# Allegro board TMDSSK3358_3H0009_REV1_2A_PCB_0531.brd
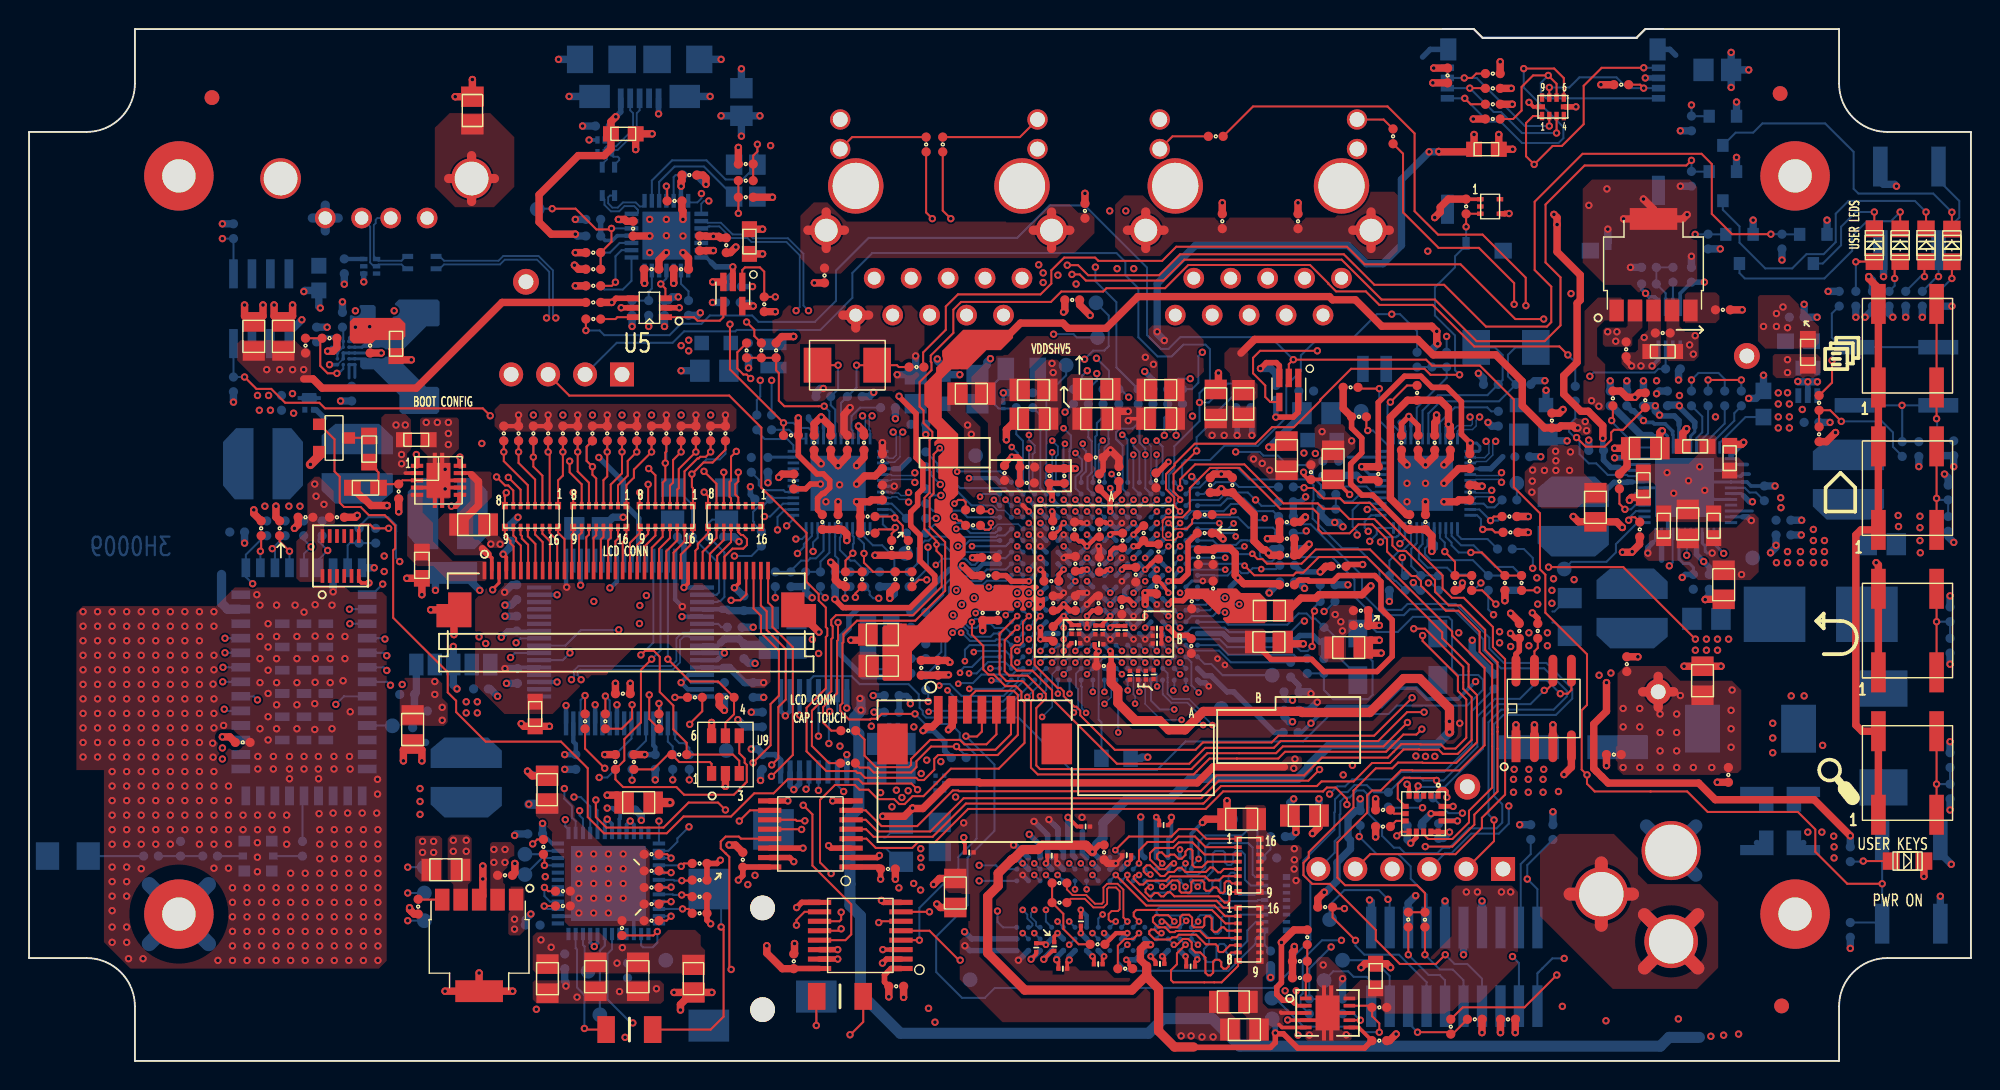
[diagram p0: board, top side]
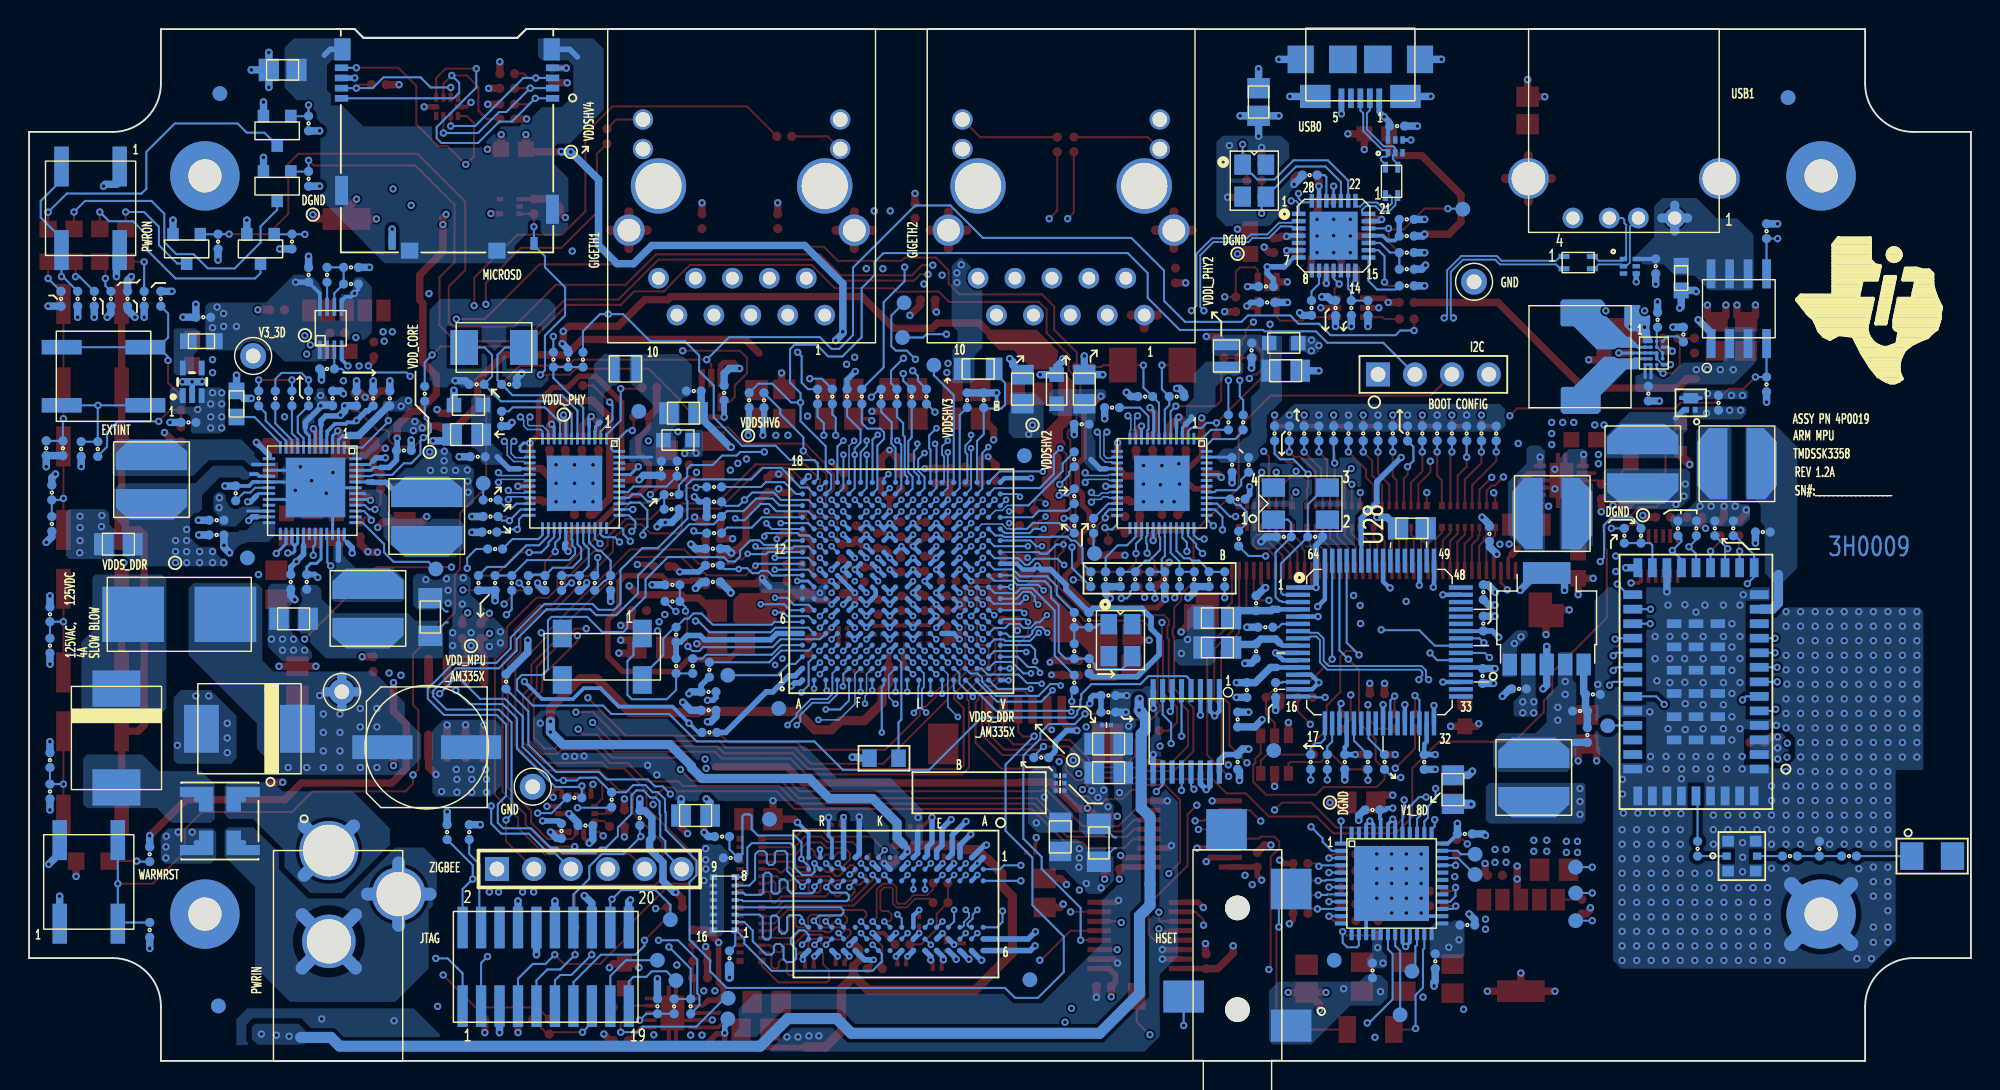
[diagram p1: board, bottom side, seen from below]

Outline 133.51 x 71.01 mm; copper layers: TOP, LY2_GND1, LY3_SIG1, LYR4_PWR1, LY5_PWR2, LY6_SIG2, LY7_GND2, BOTTOM. Coordinates in mm from the lower left corner of the outline.
Outline path: 0,63.93 3.95,63.93 arc(6.3,64.9) 7.28,67.25 7.28,71.01 99.33,71.01 99.93,70.41 110.53,70.41 111.13,71.01 124.45,71.01 124.45,67.25 arc(125.42,64.9) 127.78,63.93 133.51,63.93 133.51,7.08 127.78,7.08 arc(125.42,6.11) 124.45,3.76 124.45,0 7.28,0 7.28,3.76 arc(6.3,6.11) 3.95,7.08 0,7.08 0,63.93

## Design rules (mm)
net group AM335X_RGMII1_RXCLK: nets AM335X_RGMII1_RXCLK ETH1_RXCLK
net group AM335X_RGMII1_RXD0: nets AM335X_RGMII1_RXD0 ETH1_RXD0
net group AM335X_RGMII1_RXD1: nets AM335X_RGMII1_RXD1 ETH1_RXD1
net group AM335X_RGMII1_RXD2: nets AM335X_RGMII1_RXD2 ETH1_RXD2
net group AM335X_RGMII1_RXD3: nets AM335X_RGMII1_RXD3 ETH1_RXD3
net group AM335X_RGMII1_RXDV: nets AM335X_RGMII1_RXDV ETH1_RXDV
net group AM335X_RGMII1_TXCLK: nets AM335X_RGMII1_TXCLK RGMII1_TXCLK
net group AM335X_RGMII1_TXD0: nets AM335X_RGMII1_TXD0 RGMII1_TXD0
net group AM335X_RGMII1_TXD1: nets AM335X_RGMII1_TXD1 RGMII1_TXD1
net group AM335X_RGMII1_TXD2: nets AM335X_RGMII1_TXD2 RGMII1_TXD2
net group AM335X_RGMII1_TXD3: nets AM335X_RGMII1_TXD3 RGMII1_TXD3
net group AM335X_RGMII1_TXEN: nets AM335X_RGMII1_TXEN RGMII1_TXEN
net group AM335X_RGMII2_RXCLK: nets AM335X_RGMII2_RXCLK ETH2_RXCLK
net group AM335X_RGMII2_RXD0: nets AM335X_RGMII2_RXD0 ETH2_RXD0
net group AM335X_RGMII2_RXD1: nets AM335X_RGMII2_RXD1 ETH2_RXD1
net group AM335X_RGMII2_RXD2: nets AM335X_RGMII2_RXD2 ETH2_RXD2
net group AM335X_RGMII2_RXD3: nets AM335X_RGMII2_RXD3 ETH2_RXD3
net group AM335X_RGMII2_RXDV: nets AM335X_RGMII2_RXDV ETH2_RXDV
net group AM335X_RGMII2_TXCLK: nets AM335X_RGMII2_TXCLK RGMII2_TXCLK
net group AM335X_RGMII2_TXD0: nets AM335X_RGMII2_TXD0 RGMII2_TXD0
net group AM335X_RGMII2_TXD1: nets AM335X_RGMII2_TXD1 RGMII2_TXD1
net group AM335X_RGMII2_TXD2: nets AM335X_RGMII2_TXD2 RGMII2_TXD2
net group AM335X_RGMII2_TXD3: nets AM335X_RGMII2_TXD3 RGMII2_TXD3
net group AM335X_RGMII2_TXEN: nets AM335X_RGMII2_TXEN RGMII2_TXEN
net group BYTE2: nets DDR_DQS1 DDR_DQSN1
net group CLK_25M: nets CLK_25M CLK_25M_R
net group ETHER2_D0: nets ETHER2_D0N ETHER2_D0P
net group ETHER2_D1: nets ETHER2_D1N ETHER2_D1P
net group ETHER2_D2: nets ETHER2_D2N ETHER2_D2P
net group ETHER2_D3: nets ETHER2_D3N ETHER2_D3P
net group ETHER_D0: nets ETHER_D0N ETHER_D0P
net group ETHER_D1: nets ETHER_D1N ETHER_D1P
net group ETHER_D2: nets ETHER_D2N ETHER_D2P
net group ETHER_D3: nets ETHER_D3N ETHER_D3P
net group HUB_USB_UP: nets HUB_USBDM_UP HUB_USBDP_UP
net group USB0_DP1: nets USB0_DM USB0_DP
net group USB0_UP_DP1: nets USBDM_UP USBDP_UP
net group USB1_CONN_DP_1: nets USB1_CONN_DM USB1_CONN_DP
net group USB1_DIP1: nets USB1_DM USB1_DP
net group USB_FT_DP1: nets FT_DM FT_DP
net group ADD: nets DDR_A0 DDR_A1 DDR_A2 DDR_A3 DDR_A4 DDR_A5 DDR_A6 DDR_A7 DDR_A8 DDR_A9 DDR_A10 DDR_A11 DDR_A12 DDR_A13 DDR_A14 DDR_BA0 DDR_BA1 DDR_BA2 DDR_CASN DDR_CKE DDR_CSN DDR_ODT DDR_RASN DDR_RESETN DDR_WEN
net group AUDIO: nets AM335X_AUDA_DIN AM335X_AUDA_DOUT AM335X_AUDA_FSX AM335X_XDMA_EVENT_INTR0 AM335X_XDMA_EVENT_INTR1 AUD_RESETN HD_SPKRM HD_SPKRP HS_SPKRM HS_SPKRP SYS_WARMRESETN
net group BYTE0: nets DDR_D0 DDR_D1 DDR_D2 DDR_D3 DDR_D4 DDR_D5 DDR_D6 DDR_D7 DDR_DQM0
net group BYTE1: nets DDR_D8 DDR_D9 DDR_D10 DDR_D11 DDR_D12 DDR_D13 DDR_D14 DDR_D15 DDR_DQM1 DDR_DQS0 DDR_DQSN0
net group CLK: nets AM335X_AUDA_BCLK AM335X_LCD_PCLK AM335X_MCASP0_ACLKX AM335X_MCASP0_AHCLKR AM335X_MCASP0_AHCLKX AM335X_MMC0_CLK AM335X_OSC1_IN AM335X_OSC1_OUT AM335X_RGMII1_MDIO_CLK AM335X_SPI0_SCLK CCLK COM_SLOW_CLK COM_SLOW_CLK_XO COMAUD_CLK ETH_MDIO_CLK JTAG_TCK MMC1_CLK
net group DDR: nets N21689199 N24290596 N24874310 REFIN_DDR
net group LCD_IF: nets AM335X_LCD_AC_BIAS_EN AM335X_LCD_DATA0 AM335X_LCD_DATA1 AM335X_LCD_DATA2 AM335X_LCD_DATA3 AM335X_LCD_DATA4 AM335X_LCD_DATA5 AM335X_LCD_DATA6 AM335X_LCD_DATA7 AM335X_LCD_DATA8 AM335X_LCD_DATA9 AM335X_LCD_DATA10 AM335X_LCD_DATA11 AM335X_LCD_DATA12 AM335X_LCD_DATA13 AM335X_LCD_DATA14 AM335X_LCD_DATA15 AM335X_LCD_DATA16 AM335X_LCD_DATA17 AM335X_LCD_DATA18 AM335X_LCD_DATA19 AM335X_LCD_DATA20 AM335X_LCD_DATA21 AM335X_LCD_DATA22 AM335X_LCD_DATA23 AM335X_LCD_DISEN AM335X_LCD_HSYNC AM335X_LCD_VSYNC AM335X_XLEFT AM335X_XRIGHT AM335X_YDOWN AM335X_YUP CBB0 CBB1 CBB2 CBB3 CBB4 CBB5 CBB6 CBB7 CBG0 CBG1 CBG2 CBG3 CBG4 CBG5 CBG6 CBG7 CBR0 CBR1 CBR2 CBR3 CBR4 CBR5 CBR6 CBR7 CDEN CHSYNC CVSYNC DISEN LCD_BACKLIGHTEN
net group POWER: nets CAP_VDD_SRAM_CORE DDR_VREF GNDA_ADC VBUS_DET
net group PWR: nets CAP_VBB_MPU CAP_VDD_SRAM_MPU CHASSIS_USB0 FT_VBUS GND_IN GND_OSC0 GND_OSC1 KEYPAD_PWRA LED+ LED- N21904036 N21904046 N27067217 PWR_SMPS1 PWR_SMPS1_FB PWR_SMPS2 PWR_SWIO USB_DC V5_0D VAUX1 VCOM_BATFB VDD_1V8FT VDD_FTVPHY VDD_FTVPLL VDD_MPU_AM335X VDD_RTC VDDH_PHY VDDH_PHY2 VDDL_PHY2 VDDMPU_MON VDDS_DDR3_AM335X VDDSHV1 VETH2_AVDD_3_3 VETH2_VDDIO VETH_VDDIO VRTC_PMIC
net group RF_SIGNALS: nets N21930813 N21931209 N21931218 N23618396

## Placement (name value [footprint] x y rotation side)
A1  LBEE5ZSTNC-523  [MOD17X10-62P]  18.9 26.09 0 bottom
ANT1  LDA312G7313F-237  [SMD1206-ANTENNA]  2.67 14.1 180 bottom
C1  0.1uF  [SM-7351-CAP-0402]  97.54 67.82 270 top
C2  4.7uF  [SM-7351-CAP-0603]  40.86 63.8 0 top
C3  4.7uF  [SM-7351-CAP-0603]  100.2 62.74 0 top
C4  18pF, 10V, 2%  [SM-7351-CAP-0402]  49.28 61.72 0 top
C5  0.1uF  [SM-7351-CAP-0402]  45.4 60.96 0 top
C6  18pF, 10V, 2%  [SM-7351-CAP-0402]  49.28 59.44 180 top
C7  1uF  [SM-7351-CAP-0402]  44.38 59.18 0 top
C8  0.1uF  [SM-7351-CAP-0402]  72.6 58.5 270 top
C9  0.1uF  [SM-7351-CAP-0402]  82.04 57.78 270 top
C10  0.1uF  [SM-7351-CAP-0402]  87.25 57.78 270 top
C11  0.1uF  [SM-7351-CAP-0402]  41.53 57.28 270 top
C12  4.7uF  [SM-7351-CAP-0603]  49.53 56.39 270 top
C13  0.1uF  [SM-7351-CAP-0402]  46.1 56.26 270 top
C14  1uF  [SM-7351-CAP-0402]  47.94 56.13 270 top
C15  0.1uF  [SM-7351-CAP-0402]  42.8 54.48 0 top
C16  0.1uF  [SM-7351-CAP-0402]  44.83 54.48 0 top
C17  0.1uF  [SM-7351-CAP-0402]  54.69 54.05 90 top
C18  0.1uF  [SM-7351-CAP-0402]  71.72 52.37 0 top
C19  0.01uF  [SM-7351-CAP-0402]  116.46 51.69 0 top
C20  0.01uF  [SM-7351-CAP-0402]  112.33 50.1 180 top
C21  22uF  [SM-7351-CAP-0805]  15.45 49.86 90 top
C22  22uF  [SM-7351-CAP-0805]  17.48 49.86 90 top
C23  4.7uF  [SM-7351-CAP-0603]  25.23 49.35 270 top
C24  0.1uF  [SM-7351-CAP-0402]  23.45 49.23 270 top
C25  2.2uF, 10V  [SM-7351-CAP-0402]  109.81 48.97 270 top
C26  4.7uF  [SM-7351-CAP-0603]  112.33 48.83 180 top
C27  10uF  [SM-7351-CAP-0805]  81.59 45.21 90 top
C28  10uF  [SM-7351-CAP-0805]  69.09 44.2 180 top
C29  10uF  [SM-7351-CAP-0805]  73.41 44.2 0 top
C30  10uF  [SM-7351-CAP-0805]  77.8 44.2 180 top
C31  2.2uF  [SM-7351-CAP-0402]  104.71 44.07 90 top
C32  1uF  [SM-7351-CAP-0402]  123.08 43.12 270 top
C33  4.7uF  [SM-7351-CAP-0603]  26.63 42.75 0 top
C34  0.1uF  [SM-7351-CAP-0402]  53.97 42.55 270 top
C35  1uF  [SM-7351-CAP-0402]  55.12 42.55 270 top
C36  0.1uF  [SM-7351-CAP-0402]  56.26 42.55 270 top
C37  1uF  [SM-7351-CAP-0402]  57.4 42.55 270 top
C38  0.1uF  [SM-7351-CAP-0402]  94.36 42.55 270 top
C39  1uF  [SM-7351-CAP-0402]  95.5 42.55 270 top
C40  0.1uF  [SM-7351-CAP-0402]  96.65 42.55 270 top
C41  1uF  [SM-7351-CAP-0402]  97.72 42.55 270 top
C42  4.7uF  [SM-7351-CAP-0603]  114.55 42.29 0 top
C43  10uF  [SM-7351-CAP-0805]  111.12 42.16 180 top
C44  10uF  [SM-7351-CAP-0805]  86.46 41.66 90 top
C45  0.01uF  [SM-7351-CAP-0402]  73.34 41.53 0 top
C46  4.7uF  [SM-7351-CAP-0603]  116.92 41.48 270 top
C47  0.1uF  [SM-7351-CAP-0402]  58.67 41.27 270 top
C48  0.1uF  [SM-7351-CAP-0402]  99.06 41.27 270 top
C49  10uF  [SM-7351-CAP-0805]  89.66 41.02 90 top
C50  0.01uF  [SM-7351-CAP-0402]  68.63 40.87 180 top
C51  0.01uF  [SM-7351-CAP-0402]  88.14 40.51 90 top
C52  0.01uF  [SM-7351-CAP-0402]  67.07 40.46 90 top
C53  0.01uF  [SM-7351-CAP-0402]  74.93 40.39 90 top
C54  0.1uF  [SM-7351-CAP-0402]  92.77 40.39 270 top
C55  0.01uF  [SM-7351-CAP-0402]  70.16 40.26 90 top
C56  0.01uF  [SM-7351-CAP-0402]  71.18 40.26 90 top
C57  0.01uF  [SM-7351-CAP-0402]  77.48 39.95 90 top
C58  0.1uF  [SM-7351-CAP-0402]  52.58 39.88 270 top
C59  0.01uF  [SM-7351-CAP-0402]  73.59 39.88 90 top
C60  0.01uF  [SM-7351-CAP-0402]  68.61 39.78 180 top
C61  0.01uF  [SM-7351-CAP-0402]  81.21 39.62 90 top
C62  0.01uF  [SM-7351-CAP-0402]  82.73 39.62 90 top
C63  4.7uF  [SM-7351-CAP-0603]  111 39.62 90 top
C64  47nF  [SM-7351-CAP-0402]  25.41 39.19 270 top
C65  0.1uF  [SM-7351-CAP-0402]  58.67 39.12 270 top
C66  0.1uF  [SM-7351-CAP-0402]  99.06 39.12 270 top
C67  10uF  [SM-7351-CAP-0805]  107.7 38.1 270 top
C68  470pF  [SM-7351-CAP-0402]  57.66 37.47 180 top
C69  0.01uF  [SM-7351-CAP-0402]  19.01 37.41 180 top
C70  0.01uF  [SM-7351-CAP-0402]  21.16 37.41 0 top
C71  0.1uF  [SM-7351-CAP-0402]  55.63 37.08 90 top
C72  0.01uF  [SM-7351-CAP-0402]  86.49 37.08 0 top
C73  0.1uF  [SM-7351-CAP-0402]  96.01 37.08 90 top
C74  10uF  [SM-7351-CAP-0805]  114.05 36.96 90 top
C75  4.7uF  [SM-7351-CAP-0805]  30.56 36.91 0 top
C76  4.7uF  [SM-7351-CAP-0603]  112.39 36.83 90 top
C77  4.7uF  [SM-7351-CAP-0603]  115.82 36.83 90 top
C78  0.01uF  [SM-7351-CAP-0402]  70.38 36.65 270 top
C79  0.01uF  [SM-7351-CAP-0402]  71.88 36.58 270 top
C80  0.01uF  [SM-7351-CAP-0402]  73.59 36.58 270 top
C81  470pF  [SM-7351-CAP-0402]  57.66 36.32 180 top
C82  0.01uF  [SM-7351-CAP-0402]  76.64 36.32 270 top
C83  1uF  [SM-7351-CAP-0402]  80.83 36.32 0 top
C84  0.01uF  [SM-7351-CAP-0402]  86.49 35.94 0 top
C85  0.01uF  [SM-7351-CAP-0402]  75.18 35.81 270 top
C86  0.01uF  [SM-7351-CAP-0402]  77.65 35.05 90 top
C87  0.01uF  [SM-7351-CAP-0402]  86.49 34.8 0 top
C88  0.001uF  [SM-7351-CAP-0402]  80.39 34.67 90 top
C89  0.1uF  [SM-7351-CAP-0402]  81.41 34.67 90 top
C90  0.01uF  [SM-7351-CAP-0402]  66.02 34.65 180 top
C91  0.01uF  [SM-7351-CAP-0402]  71.94 34.21 270 top
C92  0.01uF  [SM-7351-CAP-0402]  73.59 34.16 270 top
C93  0.01uF  [SM-7351-CAP-0402]  90.04 34.04 0 top
C94  0.01uF  [SM-7351-CAP-0402]  76.09 33.46 90 top
C95  0.01uF  [SM-7351-CAP-0402]  65.97 33.4 180 top
C96  0.01uF  [SM-7351-CAP-0402]  70.29 33.02 0 top
C97  10uF  [SM-7351-CAP-0805]  116.52 32.77 270 top
C98  0.01uF  [SM-7351-CAP-0402]  77.53 32.64 90 top
C99  0.01uF  [SM-7351-CAP-0402]  79.94 31.62 270 top
C100  0.01uF  [SM-7351-CAP-0402]  70.42 31.5 270 top
C101  0.01uF  [SM-7351-CAP-0402]  71.94 31.5 270 top
C102  0.01uF  [SM-7351-CAP-0402]  73.53 31.5 270 top
C103  0.01uF  [SM-7351-CAP-0402]  75.13 31.24 90 top
C104  0.01uF  [SM-7351-CAP-0402]  91.57 30.99 0 top
C105  0.01uF  [SM-7351-CAP-0402]  65.56 30.84 270 top
C106  0.01uF  [SM-7351-CAP-0402]  66.61 30.84 270 top
C107  0.01uF  [SM-7351-CAP-0402]  91.57 29.97 0 top
C108  0.1uF, 6.3V  [SMD0201]  77.55 29.77 0 top
C109  0.1uF, 6.3V  [SMD0201]  71.69 29.69 90 top
C110  0.1uF, 6.3V  [SMD0201]  72.19 29.69 90 top
C111  0.1uF, 6.3V  [SMD0201]  73.31 29.67 90 top
C112  0.1uF, 6.3V  [SMD0201]  73.82 29.67 90 top
C113  0.1uF, 6.3V  [SMD0201]  74.86 29.64 90 top
C114  0.1uF, 6.3V  [SMD0201]  75.37 29.64 90 top
C115  0.01uF  [SM-7351-CAP-0402]  102.46 29.59 90 top
C116  0.01uF  [SM-7351-CAP-0402]  70.42 29.39 90 top
C117  10uF  [SM-7351-CAP-0805]  58.67 29.34 180 top
C118  0.1uF, 6.3V  [SMD0201]  77.55 29.26 0 top
C119  0.1uF, 6.3V  [SMD0201]  71.96 28.75 180 top
C120  0.1uF, 6.3V  [SMD0201]  77.55 28.73 0 top
C121  0.1uF, 6.3V  [SMD0201]  73.56 28.68 180 top
C122  1uF  [SM-7351-CAP-0402]  79.91 28.55 270 top
C123  10uF  [SM-7351-CAP-0805]  90.74 28.45 0 top
C124  0.1uF  [SM-7351-CAP-0402]  109.85 27.3 90 top
C125  0.1uF  [SM-7351-CAP-0402]  73.89 27.18 180 top
C126  0.01uF  [SM-7351-CAP-0402]  61.34 27.05 90 top
C127  0.01uF  [SM-7351-CAP-0402]  62.48 27.05 90 top
C128  0.1uF, 6.3V  [SMD0201]  77.32 26.59 270 top
C129  0.1uF, 6.3V  [SMD0201]  75.69 26.54 270 top
C130  0.1uF, 6.3V  [SMD0201]  76.25 26.54 270 top
C131  0.1uF, 6.3V  [SMD0201]  76.78 26.54 270 top
C132  10uF  [SM-7351-CAP-0805]  115.06 26.16 90 top
C133  0.1uF  [SM-7351-CAP-0402]  40.82 25.27 180 top
C134  4.7uF  [SM-7351-CAP-0603]  34.8 23.88 270 top
C135  2.2uF  [SM-7351-CAP-0805]  26.37 22.81 270 top
C136  0.01uF  [SM-7351-CAP-0402]  14.69 21.92 0 top
C137  1uF  [SM-7351-CAP-0402]  108.97 21.08 180 top
C138  0.1uF  [SM-7351-CAP-0402]  116.84 19.69 270 top
C139  10uF  [SM-7351-CAP-0805]  41.91 17.78 0 top
C140  10uF  [SM-7351-CAP-0805]  87.69 16.89 0 top
C141  10uF  [SM-7351-CAP-0805]  83.37 16.64 180 top
C142  0.1uF, 6.3V  [SMD0201]  78.01 16.23 0 top
C143  0.1uF, 6.3V  [SMD0201]  72.64 16.13 0 top
C144  0.1uF, 6.3V  [SMD0201]  64.64 14.35 0 top
C145  0.1uF  [SM-7351-CAP-0402]  73.91 14.35 270 top
C146  0.1uF  [SM-7351-CAP-0402]  42.8 14.22 180 top
C147  0.1uF, 6.3V  [SMD0201]  75.47 14.15 180 top
C148  0.1uF, 6.3V  [SMD0201]  70.31 14.12 0 top
C149  0.01uF  [SM-7351-CAP-0402]  49.07 13.84 90 top
C150  0.1uF  [SM-7351-CAP-0402]  46.1 13.59 0 top
C151  0.01uF  [SM-7351-CAP-0402]  59.05 13.21 0 top
C152  2.2uF  [SM-7351-CAP-0805]  28.66 13.16 180 top
C153  0.1uF  [SM-7351-CAP-0402]  42.8 13.08 180 top
C154  1uF  [SM-7351-CAP-0402]  32.72 12.78 0 top
C155  0.1uF  [SM-7351-CAP-0402]  46.1 12.45 0 top
C156  0.01uF  [SM-7351-CAP-0402]  42.8 11.94 180 top
C157  0.01uF  [SM-7351-CAP-0402]  36.7 11.68 0 top
C158  10uF  [SM-7351-CAP-0805]  63.68 11.56 90 top
C159  0.01uF  [SM-7351-CAP-0402]  46.1 11.3 0 top
C160  0.01uF  [SM-7351-CAP-0402]  42.8 10.79 180 top
C161  0.01uF  [SM-7351-CAP-0402]  36.7 10.67 0 top
C162  0.01uF  [SM-7351-CAP-0402]  26.75 10.62 270 top
C163  0.01uF  [SM-7351-CAP-0402]  46.1 10.16 0 top
C164  0.01uF  [SM-7351-CAP-0402]  42.8 9.65 180 top
C165  0.1uF, 6.3V  [SMD0201]  72.32 9.6 270 top
C166  0.01uF  [SM-7351-CAP-0402]  40.77 9.14 90 top
C167  0.1uF  [SM-7351-CAP-0402]  73.46 8.03 0 top
C168  0.1uF, 6.3V  [SMD0201]  70.48 7.87 90 top
C169  0.1uF, 6.3V  [SMD0201]  69.25 7.8 90 top
C170  0.01uF  [SM-7351-CAP-0402]  52.58 6.86 90 top
C171  0.001uF  [SM-7351-CAP-0402]  87.38 6.86 180 top
C172  0.1uF, 6.3V  [SMD0201]  77.76 6.68 0 top
C173  0.1uF, 6.3V  [SMD0201]  73.51 6.65 180 top
C174  0.1uF, 6.3V  [SMD0201]  79.86 6.5 0 top
C175  0.1uF, 6.3V  [SMD0201]  71.08 6.35 0 top
C176  4.7uF  [SM-7351-CAP-0603]  92.58 5.84 90 top
C177  10uF  [SM-7351-CAP-0805]  38.94 5.79 270 top
C178  10uF  [SM-7351-CAP-0805]  41.87 5.79 270 top
C179  10uF  [SM-7351-CAP-0805]  35.64 5.66 270 top
C180  0.01uF  [SM-7351-CAP-0402]  59.62 5.14 0 top
C181  47uF  [SM-7351-CAP-1206]  55.75 4.45 0 top
C182  10uF  [SM-7351-CAP-0805]  82.8 4.06 180 top
C183  0.1uF  [SM-7351-CAP-0402]  99.4 2.87 0 top
C184  0.01uF  [SM-7351-CAP-0402]  101.69 2.87 180 top
C185  47uF  [SM-7351-CAP-1206]  41.27 2.16 180 top
C186  10uF  [SM-7351-CAP-0805]  83.57 2.16 180 top
C187  0.1uF  [SM-7351-CAP-0402]  92.84 1.4 0 top
C188  0.01uF  [SM-7351-CAP-0402]  39.45 64.34 180 bottom
C189  0.1uF  [SM-7351-CAP-0402]  38.79 55.63 180 bottom
C190  0.01uF  [SM-7351-CAP-0402]  21.67 54.69 270 bottom
C191  0.01uF  [SM-7351-CAP-0402]  111.38 54.61 180 bottom
C192  0.01uF  [SM-7351-CAP-0402]  114.3 54.1 90 bottom
C193  4.7uF  [SM-7351-CAP-0603]  19.92 53.87 270 bottom
C194  0.1uF  [SM-7351-CAP-0402]  48.39 52.2 0 bottom
C195  1uF  [SM-7351-CAP-0402]  45.34 51.82 270 bottom
C196  0.1uF  [SM-7351-CAP-0402]  43.69 51.82 90 bottom
C197  1uF  [SM-7351-CAP-0402]  121.54 51.18 0 bottom
C198  0.1uF  [SM-7351-CAP-0402]  21.55 51 90 bottom
C199  0.1uF  [SM-7351-CAP-0402]  49.46 48.89 270 bottom
C200  10uF  [SM-7351-CAP-0805]  47.12 47.5 180 bottom
C201  27pF  [SM-7351-CAP-0402]  102.74 46.56 180 bottom
C202  27pF  [SM-7351-CAP-0402]  100.51 46.56 0 bottom
C203  10uF  [SM-7351-CAP-0805]  65.21 46.23 90 bottom
C204  10uF  [SM-7351-CAP-0805]  60.96 46.23 90 bottom
C205  0.1uF  [SM-7351-CAP-0402]  87.81 46.1 180 bottom
C206  0.01uF  [SM-7351-CAP-0402]  85.72 45.97 90 bottom
C207  2.2uF, 10V  [SM-7351-CAP-0402]  22.18 45.92 270 bottom
C208  27pF  [SM-7351-CAP-0402]  56.77 45.72 180 bottom
C209  27pF  [SM-7351-CAP-0402]  54.61 45.72 0 bottom
C210  2.2uF  [SM-7351-CAP-0402]  112.65 45.59 90 bottom
C211  2.2uF  [SM-7351-CAP-0402]  111 45.59 90 bottom
C212  2.2uF  [SM-7351-CAP-0402]  109.85 45.59 90 bottom
C213  2.2uF  [SM-7351-CAP-0402]  108.71 45.59 90 bottom
C214  0.1uF  [SM-7351-CAP-0402]  67.88 45.47 90 bottom
C215  0.01uF  [SM-7351-CAP-0402]  17.35 45.29 90 bottom
C216  10uF  [SM-7351-CAP-0805]  88.52 44.58 180 bottom
C217  1uF  [SM-7351-CAP-0402]  122.55 43.94 0 bottom
C218  0.1uF  [SM-7351-CAP-0402]  61.14 43.81 0 bottom
C219  10uF  [SM-7351-CAP-0805]  103.43 43.1 0 bottom
C220  1uF  [SM-7351-CAP-0402]  132.33 42.16 270 bottom
C221  2.2uF  [SM-7351-CAP-0402]  107.75 42.01 180 bottom
C222  0.1uF  [SM-7351-CAP-0402]  102.67 41.58 0 bottom
C223  0.1uF  [SM-7351-CAP-0402]  50.8 41.02 270 bottom
C224  0.1uF  [SM-7351-CAP-0402]  90.04 40.77 270 bottom
C225  0.01uF  [SM-7351-CAP-0402]  119.31 39.06 90 bottom
C226  470pF  [SM-7351-CAP-0402]  101.78 37.47 0 bottom
C227  2.2uF  [SM-7351-CAP-0402]  120.62 37.21 0 bottom
C228  1uF  [SM-7351-CAP-0402]  131.95 36.96 270 bottom
C229  470pF  [SM-7351-CAP-0402]  101.86 36.4 0 bottom
C230  0.01uF  [SM-7351-CAP-0402]  14.31 36.4 0 bottom
C231  0.01uF  [SM-7351-CAP-0402]  33.1 36.27 90 bottom
C232  2.2uF  [SM-7351-CAP-0402]  120.62 36.2 0 bottom
C233  27pF  [SM-7351-CAP-0402]  47.24 36.07 180 bottom
C234  27pF  [SM-7351-CAP-0402]  45.08 36.07 0 bottom
C235  10uF  [SM-7351-CAP-0805]  127.38 35.56 0 bottom
C236  0.01uF  [SM-7351-CAP-0402]  86.5 35.25 0 bottom
C237  470pF  [SM-7351-CAP-0402]  59.49 33.15 270 bottom
C238  2.2uF  [SM-7351-CAP-0402]  115.53 32.97 270 bottom
C239  0.01uF  [SM-7351-CAP-0402]  86.5 32.96 0 bottom
C240  470pF  [SM-7351-CAP-0402]  102.62 32.89 270 bottom
C241  0.1uF  [SM-7351-CAP-0402]  33.53 32.26 90 bottom
C242  0.1uF  [SM-7351-CAP-0402]  49.15 31.5 90 bottom
C243  1uF  [SM-7351-CAP-0402]  132.08 30.73 90 bottom
C244  10uF  [SM-7351-CAP-0805]  115.33 30.42 0 bottom
C245  18pF, 50V  [SM-7351-CAP-0402]  60.64 30.35 270 bottom
C246  0.1uF  [SM-7351-CAP-0402]  33.53 30.1 90 bottom
C247  22pF  [SM-7351-CAP-0402]  89.03 29.34 90 bottom
C248  0.1uF  [SM-7351-CAP-0402]  49.15 28.19 270 bottom
C249  22pF  [SM-7351-CAP-0402]  89.03 27.18 270 bottom
C250  18pF, 50V  [SM-7351-CAP-0402]  60.64 27.18 90 bottom
C251  0.1uF  [SM-7351-CAP-0402]  33.58 26.49 90 bottom
C252  1uF  [SM-7351-CAP-0402]  31.07 25.6 0 bottom
C253  0.1uF  [SM-7351-CAP-0402]  49.78 25.53 90 bottom
C254  1uF  [SM-7351-CAP-0402]  86.8 25.4 0 bottom
C255  0.01uF  [SM-7351-CAP-0402]  59.31 25.15 180 bottom
C256  1uF  [SM-7351-CAP-0402]  86.8 24.13 0 bottom
C257  15pF  [SM-7351-CAP-0402]  26.88 24.08 180 bottom
C258  0.01uF  [SM-7351-CAP-0402]  59.31 24 180 bottom
C259  0.01uF  [SM-7351-CAP-0402]  50.42 23.49 90 bottom
C260  0.1uF, 6.3V  [SMD0201]  59.44 23.11 180 bottom
C261  10uF  [SM-7351-CAP-0805]  59.28 21.82 180 bottom
C262  100uF  [SM-7351-CAP-SMDCAN]  106.17 21.59 0 bottom
C263  1uF  [SM-7351-CAP-0402]  132.08 20.7 90 bottom
C264  0.01uF  [SM-7351-CAP-0402]  50.42 20.57 270 bottom
C265  0.1uF  [SM-7351-CAP-0402]  43.05 20.57 270 bottom
C266  0.1uF  [SM-7351-CAP-0402]  37.59 20.57 270 bottom
C267  10uF  [SM-7351-CAP-0805]  59.28 19.84 180 bottom
C268  0.1uF, 6.3V  [SMD0201]  62.62 19.63 0 bottom
C269  0.1uF, 6.3V  [SMD0201]  62.62 19.12 0 bottom
C270  10uF  [SM-7351-CAP-0805]  35.62 18.67 90 bottom
C271  0.1uF, 6.3V  [SMD0201]  62.62 18.61 0 bottom
C272  0.1uF  [SM-7351-CAP-0402]  41.15 17.27 0 bottom
C273  10uF  [SM-7351-CAP-0805]  87.69 16.89 0 bottom
C274  0.01uF  [SM-7351-CAP-0402]  95.26 16.2 180 bottom
C275  0.01uF  [SM-7351-CAP-0402]  96.91 15.82 270 bottom
C276  0.1uF  [SM-7351-CAP-0402]  34.8 15.62 180 bottom
C277  10uF  [SM-7351-CAP-0805]  62.62 15.42 90 bottom
C278  0.1uF  [SM-7351-CAP-0402]  34.63 9.35 180 bottom
C279  1uF  [SM-7351-CAP-0402]  125.22 9.02 270 bottom
C280  0.1uF  [SM-7351-CAP-0402]  36.83 6.86 270 bottom
C281  0.1uF  [SM-7351-CAP-0402]  41.15 6.22 270 bottom
D1  Green LED  [SM_LED_0805]  126.87 56.13 90 top
D2  Green LED  [SM_LED_0805]  128.65 56.13 90 top
D3  Green LED  [SM_LED_0805]  130.43 56.13 90 top
D4  Green LED  [SM_LED_0805]  132.21 56.12 90 top
D5  Green LED  [SM_LED_0805]  129.16 13.75 0 top
D6  GDZT2R5.1  [GMD2_2PIN]  66.99 45.08 180 bottom
D7  SMCJ7.0CA  [SMCJ15CA]  118.36 22.86 0 bottom
D8  -  [B520C-13-F]  127.51 22.23 270 bottom
F1  Fuse 4A  [SMDFUSEBLK]  123.19 30.73 180 bottom
FB1  150OHM800mA  [SM-7351-IND-0805]  30.48 65.41 270 top
FB2  150OHM800mA  [SM-7351-IND-0805]  73.41 46.23 0 top
FB3  150OHM800mA  [SM-7351-IND-0805]  69.06 46.18 180 top
FB4  150OHM800mA  [SM-7351-IND-0805]  77.8 46.18 180 top
FB5  150OHM800mA  [SM-7351-IND-0805]  64.78 45.92 0 top
FB6  150OHM800mA  [SM-7351-IND-0805]  83.5 45.21 90 top
FB7  150OHM800mA  [SM-7351-IND-0805]  85.27 30.99 0 top
FB8  150OHM800mA  [SM-7351-IND-0805]  85.25 28.83 0 top
FB9  150OHM800mA  [SM-7351-IND-0805]  58.67 27.18 180 top
FB10  150OHM800mA  [SM-7351-IND-0805]  35.62 18.67 90 top
FB11  150OHM800mA  [SM-7351-IND-0805]  45.68 5.66 90 top
FB12  150OHM800mA  [SM-7351-IND-0805]  116.08 68.2 180 bottom
FB13  150OHM800mA  [SM-7351-IND-0805]  48.98 65.99 90 bottom
FB14  600mAFB10ohm  [HF70ACB201209]  47.24 49.4 0 bottom
FB15  600mAFB10ohm  [HF70ACB201209]  62.86 46.23 270 bottom
FB16  600mAFB10ohm  [HF70ACB201209]  103.3 45.14 180 bottom
FB17  600mAFB10ohm  [HF70ACB201209]  88.9 42.72 0 bottom
FB18  150OHM800mA  [SM-7351-IND-0805]  38.44 36.65 180 bottom
FB19  150OHM800mA  [SM-7351-IND-0805]  51.82 30.48 180 bottom
FB20  150OHM800mA  [SM-7351-IND-0805]  51.82 28.45 180 bottom
J1  54132-4097  [CNFPC1X40-0P5MM]  41.06 30.17 0 top
J2  0522710679  [CN52271-0679]  65.01 19.94 0 top
J3  USB_MicroAB  [ZX62-AB-5PA]  41.98 66.25 0 bottom
J4  SCHA5B0200  [SD-MICRO-SCHA5B0300]  104.78 66.25 0 bottom
J5  USB A  [USB_STD_A_TH]  20.37 58.01 0 bottom
J6  RJ-45 Gigabit  [6605814-6]  78.81 51.33 0 bottom
J7  RJ-45 Gigabit  [6605814-6]  56.84 51.33 0 bottom
J8  HEADER 4  [HEADER_4X1]  40.77 47.24 180 bottom
J9  Power Jack RAPC712  [RAPC712]  112.9 14.48 90 bottom
J10  MM8130-2600  [CNMM8130-CUS-TI]  15.75 14.1 180 bottom
J11  HEADER 6  [HEADER_6X1]  101.35 13.21 180 bottom
J12  CTI JTAG  [HEADER10X2]  97.99 6.48 180 bottom
J13  3.5mm SJ3524  [SJ3524SMT4PIN]  46.48 2.43 270 bottom
L1  ACM2012  [ACM2012H]  39.83 60.53 90 bottom
L2  ACM2012  [ACM2012H]  27.01 54.94 180 bottom
L3  4.7uH  [MIPF2016]  51.18 48.51 270 bottom
L4  4.7uH  [SMD_SLF7055T]  26.88 48.46 270 bottom
L5  4.7uH  [MIPF2016]  92.51 47.62 0 bottom
L6  2.2uH  [VLCF5020T]  22.56 41.1 270 bottom
L7  2.2uH  [VLCF5020T]  16.08 41.1 180 bottom
L8  2.2uH  [VLCF5020T]  125.09 40 270 bottom
L9  4.7uH  [VLCF5020T]  28.78 37.67 0 bottom
L10  2.2uH  [VLCF5020T]  106.17 37.47 90 bottom
L11  2.2uH  [VLCF5020T]  110.22 31.14 270 bottom
L12  2.2uH  [VLCF5020T]  30.05 19.51 90 bottom
L13  5.1nH  [SM-7351-CAP-0402]  10.41 14.61 90 bottom
L14  0  [SM-7351-RES-0402]  12.45 14.1 180 bottom
L15  1.3nH  [SM-7351-RES-0402]  8.38 14.1 0 bottom
MH1  2.286MM_MHOLE  [MH188X90PL]  10.3 60.9 0 top
MH2  2.286MM_MHOLE  [MH188X90PL]  121.43 60.9 0 top
MH3  2.286MM_MHOLE  [MH188X90PL]  10.3 10.1 0 top
MH4  2.286MM_MHOLE  [MH188X90PL]  121.43 10.1 0 top
NOREF  -  [unnamed]  12.57 66.29 0 top
NOREF#2  -  [unnamed]  120.5 3.78 0 top
NOREF#3  -  [#2]  12.45 69.87 0 top
NOREF#4  -  [unnamed]  120.4 66.57 0 top
NOREF#5  -  [unnamed]  120.5 3.78 180 bottom
NOREF#6  -  [unnamed]  47.94 21.36 180 bottom
NOREF#7  -  [unnamed]  120.4 66.57 180 bottom
NOREF#8  -  [unnamed]  82.61 16.64 180 bottom
NOREF#9  -  [unnamed]  12.57 66.29 180 bottom
NOREF#10  -  [unnamed]  43.78 6.93 180 bottom
NOREF#11  -  [unnamed]  118.5 34.62 180 bottom
NOREF#12  -  [unnamed]  65.08 41.66 180 bottom
NOREF#13  -  [unnamed]  91.59 44.7 180 bottom
NOREF#14  -  [unnamed]  81.97 24.26 180 bottom
NOREF#15  -  [unnamed]  64.7 5.59 180 bottom
Q1  BSS138  [SOT23-3]  20.97 42.87 270 top
Q2  BSS138  [SOT23-3]  116.46 64.01 0 bottom
Q3  BSS138  [SOT23-3]  116.46 60.2 0 bottom
Q4  BSS138  [SOT23-3]  122.68 55.88 0 bottom
Q5  BSS138  [SOT23-3]  117.6 55.88 0 bottom
R1  10K  [SM-7351-RES-0402]  100.64 67.94 0 top
R2  10K  [SM-7351-RES-0402]  109.47 67.18 180 top
R3  10K  [SM-7351-RES-0402]  100.64 66.93 0 top
R4  10K  [SM-7351-RES-0402]  100.64 65.84 0 top
R5  10K  [SM-7351-RES-0402]  100.64 64.82 180 top
R6  220  [SM-7351-RES-0402]  81.59 63.63 180 top
R7  220  [SM-7351-RES-0402]  93.78 63.63 90 top
R8  220  [SM-7351-RES-0402]  61.68 63.07 90 top
R9  220  [SM-7351-RES-0402]  62.82 63.07 90 top
R10  1M  [SM-7351-RES-0402]  49.28 60.58 180 top
R11  470K  [SM-7351-RES-0402]  98.81 58.8 90 top
R12  100K  [SM-7351-RES-0402]  38.79 55.63 0 top
R13  10K, 1%  [SM-7351-RES-0402]  38.79 54.48 180 top
R14  100K  [SM-7351-RES-0402]  38.79 53.34 0 top
R15  4.7K  [SM-7351-RES-0402]  38.79 52.2 180 top
R16  4.75K, 1%  [SM-7351-RES-0402]  50.55 52.07 90 top
R17  0  [SM-7351-RES-0402]  38.79 51.05 0 top
R18  180K  [SM-7351-RES-0402]  20.66 49.73 180 top
R19  1.62M  [SM-7351-RES-0402]  19.01 49.23 270 top
R20  0  [SM-7351-RES-0402]  49.33 48.89 90 top
R21  0  [SM-7351-RES-0402]  50.35 48.89 90 top
R22  10K  [SM-7351-RES-0402]  51.37 48.89 90 top
R23  0  [SM-7351-RES-0603]  122.3 48.77 90 top
R24  22  [SM-7351-RES-0402]  61.02 47.75 0 top
R25  10K  [SM-7351-RES-0402]  90.86 46.36 0 top
R26  100K  [SM-7351-RES-0402]  95.43 45.97 90 top
R27  10K  [SM-7351-RES-0402]  108.9 45.59 90 top
R28  10K  [SM-7351-RES-0402]  111.12 45.47 90 top
R29  0  [SM-7351-RES-0402]  123.08 45.28 90 top
R30  1.5K  [SM-7351-RES-0402]  91.44 44.32 180 top
R31  10K  [SM-7351-RES-0402]  32.64 43.18 270 top
R32  10K  [SM-7351-RES-0402]  33.66 43.18 270 top
R33  10K  [SM-7351-RES-0402]  34.67 43.18 270 top
R34  10K  [SM-7351-RES-0402]  35.69 43.18 270 top
R35  10K  [SM-7351-RES-0402]  36.7 43.18 270 top
R36  10K  [SM-7351-RES-0402]  37.72 43.18 270 top
R37  10K  [SM-7351-RES-0402]  38.73 43.18 270 top
R38  10K  [SM-7351-RES-0402]  39.75 43.18 270 top
R39  10K  [SM-7351-RES-0402]  40.77 43.18 270 top
R40  10K  [SM-7351-RES-0402]  41.78 43.18 270 top
R41  10K  [SM-7351-RES-0402]  42.8 43.18 270 top
R42  10K  [SM-7351-RES-0402]  43.81 43.18 270 top
R43  10K  [SM-7351-RES-0402]  44.83 43.18 270 top
R44  10K  [SM-7351-RES-0402]  45.85 43.18 270 top
R45  10K  [SM-7351-RES-0402]  46.86 43.18 270 top
R46  10K  [SM-7351-RES-0402]  47.88 43.18 270 top
R47  100K  [SM-7351-RES-0402]  52.38 43.05 0 top
R48  10, 1%  [SM-7351-RES-0603]  23.38 42.11 90 top
R49  100K  [SM-7351-RES-0402]  109.35 39.88 270 top
R50  44.2K, 1%  [SM-7351-RES-0603]  23.13 39.44 0 top
R51  22  [SM-7351-RES-0402]  64.9 37.92 0 top
R52  22  [SM-7351-RES-0402]  80.83 37.59 180 top
R53  10K  [SM-7351-RES-0402]  101.78 37.47 180 top
R54  0  [SM-7351-RES-0402]  54.54 37.08 270 top
R55  0  [SM-7351-RES-0402]  94.93 37.08 270 top
R56  22  [SM-7351-RES-0402]  64.9 36.86 0 top
R57  10K  [SM-7351-RES-0402]  15.96 36.65 90 top
R58  10K  [SM-7351-RES-0402]  17.23 36.65 90 top
R59  10K, 1%  [SM-7351-RES-0402]  110.74 36.58 90 top
R60  10K  [SM-7351-RES-0402]  101.85 36.37 180 top
R61  10K  [SM-7351-RES-0402]  59.31 35.31 90 top
R62  10K  [SM-7351-RES-0402]  60.45 35.31 90 top
R63  10, 1%  [SM-7351-RES-0603]  27.01 34.11 90 top
R64  10K  [SM-7351-RES-0402]  56.13 33.15 90 top
R65  22  [SM-7351-RES-0402]  57.28 33.15 270 top
R66  10K  [SM-7351-RES-0402]  59.56 33.15 90 top
R67  22  [SM-7351-RES-0402]  60.71 33.15 270 top
R68  10K  [SM-7351-RES-0402]  98.04 32.89 90 top
R69  22  [SM-7351-RES-0402]  99.19 32.89 270 top
R70  10K  [SM-7351-RES-0402]  101.47 32.89 90 top
R71  22  [SM-7351-RES-0402]  102.62 32.89 270 top
R72  0  [SM-7351-RES-0402]  86.49 32.77 180 top
R73  0  [SM-7351-RES-0402]  81.41 32.51 90 top
R74  10K  [SM-7351-RES-0402]  103.73 29.59 90 top
R75  0  [SM-7351-RES-0402]  45.78 25.02 180 top
R76  10K, 1%  [SM-7351-RES-0402]  47.96 25.02 0 top
R77  0  [SM-7351-RES-0402]  38.23 23.37 90 top
R78  0  [SM-7351-RES-0402]  39.62 23.37 90 top
R79  0  [SM-7351-RES-0402]  43.31 23.37 90 top
R80  0  [SM-7351-RES-0402]  56.33 22.73 180 top
R81  2.2K  [SM-7351-RES-0402]  44.7 21.08 180 top
R82  10K, 1%  [SM-7351-RES-0402]  40.32 20.57 270 top
R83  10K, 1%  [SM-7351-RES-0402]  41.59 20.57 270 top
R84  0  [SM-7351-RES-0402]  56.3 20.49 180 top
R85  0  [SM-7351-RES-0402]  93.09 17.27 180 top
R86  10K  [SM-7351-RES-0402]  93.09 16.13 180 top
R87  0  [SM-7351-RES-0402]  35.36 14.73 90 top
R88  33  [SM-7351-RES-0402]  70.85 12.24 180 top
R89  33  [SM-7351-RES-0402]  70.85 10.9 180 top
R90  4.75K, 1%  [SM-7351-RES-0402]  89.12 10.59 0 top
R91  0  [SM-7351-RES-0402]  94.83 9.72 90 top
R92  0  [SM-7351-RES-0402]  95.97 9.72 90 top
R93  10K, 1%  [SM-7351-RES-0402]  87.88 8.51 90 top
R94  240, 1%  [SM-7351-RES-0402]  75.37 6.35 180 top
R95  10K, 1%  [SM-7351-RES-0402]  87.38 5.71 180 top
R96  10K, 1%  [SM-7351-RES-0402]  92.84 3.68 180 top
R97  100  [SM-7351-RES-0402]  97.75 2.36 90 top
R98  100K  [SM-7351-RES-0402]  114.3 64.52 90 bottom
R99  12.1K, 1%  [SM-7351-RES-0402]  45.47 60.96 0 bottom
R100  100K  [SM-7351-RES-0402]  114.3 60.71 90 bottom
R101  100K  [SM-7351-RES-0402]  38.79 57.91 0 bottom
R102  10K  [SM-7351-RES-0402]  14.05 57.1 90 bottom
R103  100K  [SM-7351-RES-0402]  38.79 56.77 180 bottom
R104  100K  [SM-7351-RES-0402]  120.52 56.39 90 bottom
R105  100K  [SM-7351-RES-0402]  115.44 56.39 90 bottom
R106  100K  [SM-7351-RES-0402]  38.79 54.48 180 bottom
R107  1K  [SM-7351-RES-0402]  113.03 54.1 270 bottom
R108  10K  [SM-7351-RES-0402]  111.38 53.47 180 bottom
R109  0  [SM-7351-RES-0402]  38.79 53.34 180 bottom
R110  10K, 1%  [SM-7351-RES-0402]  48.47 53.29 0 bottom
R111  150  [SM-7351-RES-0402]  131.32 52.45 270 bottom
R112  10K  [SM-7351-RES-0402]  130.18 52.45 270 bottom
R113  150  [SM-7351-RES-0402]  129.03 52.45 270 bottom
R114  150  [SM-7351-RES-0402]  127.89 52.45 270 bottom
R115  0  [SM-7351-RES-0402]  126.75 52.45 90 bottom
R116  150  [SM-7351-RES-0402]  125.6 52.45 270 bottom
R117  0  [SM-7351-RES-0402]  124.46 52.45 90 bottom
R118  10K, 1%  [SM-7351-RES-0402]  42.6 51.82 270 bottom
R119  10K, 1%  [SM-7351-RES-0402]  41.46 51.82 90 bottom
R120  100K  [SM-7351-RES-0402]  19.77 49.99 90 bottom
R121  0  [SM-7351-RES-0603]  121.67 49.53 0 bottom
R122  0  [SM-7351-RES-0402]  97.47 48.26 90 bottom
R123  10K  [SM-7351-RES-0402]  96.45 48.26 270 bottom
R124  0  [SM-7351-RES-0402]  95.43 48.26 90 bottom
R125  100K  [SM-7351-RES-0402]  113.03 47.62 180 bottom
R126  1.2K, 1/4W  [SM-7351-RES-0805]  68.26 47.62 180 bottom
R127  10K  [SM-7351-RES-0402]  14.05 46.56 270 bottom
R128  0  [SM-7351-RES-0402]  106.31 45.92 90 bottom
R129  22  [SM-7351-RES-0402]  79.31 45.72 270 bottom
R130  22  [SM-7351-RES-0402]  78.29 45.72 270 bottom
R131  4.7K  [SM-7351-RES-0402]  77.27 45.72 90 bottom
R132  22  [SM-7351-RES-0402]  76.26 45.72 270 bottom
R133  22  [SM-7351-RES-0402]  74.93 45.72 270 bottom
R134  22  [SM-7351-RES-0402]  73.84 45.72 270 bottom
R135  22  [SM-7351-RES-0402]  72.83 45.72 270 bottom
R136  22  [SM-7351-RES-0402]  71.81 45.72 270 bottom
R137  0  [SM-7351-RES-0402]  117.73 45.59 90 bottom
R138  0  [SM-7351-RES-0402]  116.59 45.59 90 bottom
R139  0  [SM-7351-RES-0402]  115.44 45.59 90 bottom
R140  0  [SM-7351-RES-0402]  114.3 45.59 90 bottom
R141  4.7K  [SM-7351-RES-0402]  84 45.47 270 bottom
R142  4.7K  [SM-7351-RES-0402]  82.99 45.47 270 bottom
R143  0  [SM-7351-RES-0402]  69.02 45.47 270 bottom
R144  0  [SM-7351-RES-0603]  119.25 45.21 270 bottom
R145  2.37K  [SM-7351-RES-0402]  59.05 44.96 180 bottom
R146  2.37K  [SM-7351-RES-0402]  101.02 44.2 90 bottom
R147  22  [SM-7351-RES-0402]  51.05 43.94 90 bottom
R148  22  [SM-7351-RES-0402]  50.04 43.94 90 bottom
R149  100K  [SM-7351-RES-0402]  47.88 43.18 90 bottom
R150  100K  [SM-7351-RES-0402]  46.86 43.18 90 bottom
R151  100K  [SM-7351-RES-0402]  45.85 43.18 90 bottom
R152  100K  [SM-7351-RES-0402]  44.83 43.18 90 bottom
R153  100K  [SM-7351-RES-0402]  43.81 43.18 90 bottom
R154  100K  [SM-7351-RES-0402]  42.8 43.18 90 bottom
R155  100K  [SM-7351-RES-0402]  41.78 43.18 90 bottom
R156  100K  [SM-7351-RES-0402]  40.77 43.18 90 bottom
R157  100K  [SM-7351-RES-0402]  39.75 43.18 90 bottom
R158  100K  [SM-7351-RES-0402]  38.73 43.18 90 bottom
R159  100K  [SM-7351-RES-0402]  37.72 43.18 90 bottom
R160  100K  [SM-7351-RES-0402]  36.7 43.18 90 bottom
R161  100K  [SM-7351-RES-0402]  35.69 43.18 90 bottom
R162  100K  [SM-7351-RES-0402]  34.67 43.18 90 bottom
R163  100K  [SM-7351-RES-0402]  33.66 43.18 90 bottom
R164  100K  [SM-7351-RES-0402]  32.64 43.18 90 bottom
R165  2.2K  [SM-7351-RES-0402]  131.19 42.16 90 bottom
R166  1K  [SM-7351-RES-0402]  129.93 42.11 90 bottom
R167  0  [SM-7351-RES-0402]  128.79 42.11 90 bottom
R168  22  [SM-7351-RES-0402]  61.65 41.4 90 bottom
R169  4.7K  [SM-7351-RES-0402]  49.66 41.02 270 bottom
R170  4.7K  [SM-7351-RES-0402]  88.96 40.77 270 bottom
R171  22  [SM-7351-RES-0402]  86.42 39.5 0 bottom
R172  2.2K  [SM-7351-RES-0402]  131.95 39.12 270 bottom
R173  0  [SM-7351-RES-0402]  89.34 38.99 180 bottom
R174  22  [SM-7351-RES-0402]  61.65 38.86 270 bottom
R175  10K  [SM-7351-RES-0402]  50.42 38.66 180 bottom
R176  22  [SM-7351-RES-0402]  101.78 38.61 0 bottom
R177  4.7K  [SM-7351-RES-0402]  86.42 38.48 0 bottom
R178  10K  [SM-7351-RES-0402]  89.34 37.97 0 bottom
R179  4.7K  [SM-7351-RES-0402]  86.42 37.47 0 bottom
R180  22  [SM-7351-RES-0402]  61.65 36.83 270 bottom
R181  22  [SM-7351-RES-0402]  60.33 36.83 270 bottom
R182  10K  [SM-7351-RES-0402]  20.15 36.65 90 bottom
R183  10K  [SM-7351-RES-0402]  18.88 36.65 90 bottom
R184  10K  [SM-7351-RES-0402]  17.61 36.65 90 bottom
R185  10K  [SM-7351-RES-0402]  16.34 36.65 90 bottom
R186  22  [SM-7351-RES-0402]  86.42 36.32 180 bottom
R187  0  [SM-7351-RES-0402]  23.83 36.14 90 bottom
R188  0  [SM-7351-RES-0402]  22.69 36.14 90 bottom
R189  0  [SM-7351-RES-0402]  50.35 35.94 270 bottom
R190  22  [SM-7351-RES-0402]  101.47 35.23 0 bottom
R191  10K  [SM-7351-RES-0402]  86.5 34.11 0 bottom
R192  22  [SM-7351-RES-0402]  60.51 33.15 90 bottom
R193  10K  [SM-7351-RES-0402]  58.48 33.15 90 bottom
R194  22  [SM-7351-RES-0402]  57.46 33.15 270 bottom
R195  22  [SM-7351-RES-0402]  56.45 33.15 270 bottom
R196  10K  [SM-7351-RES-0402]  55.43 33.15 90 bottom
R197  22  [SM-7351-RES-0402]  54.41 33.15 270 bottom
R198  10K  [SM-7351-RES-0402]  53.4 33.15 90 bottom
R199  10K  [SM-7351-RES-0402]  52.38 33.15 90 bottom
R200  22  [SM-7351-RES-0402]  51.31 33.15 270 bottom
R201  0  [SM-7351-RES-0402]  114.43 32.97 90 bottom
R202  10K  [SM-7351-RES-0402]  101.47 32.89 90 bottom
R203  22  [SM-7351-RES-0402]  100.33 32.89 270 bottom
R204  22  [SM-7351-RES-0402]  99.19 32.89 270 bottom
R205  10K  [SM-7351-RES-0402]  98.04 32.89 90 bottom
R206  22  [SM-7351-RES-0402]  96.9 32.89 270 bottom
R207  10K  [SM-7351-RES-0402]  95.69 32.89 90 bottom
R208  22  [SM-7351-RES-0402]  94.62 32.89 90 bottom
R209  10K  [SM-7351-RES-0402]  93.53 32.89 90 bottom
R210  0  [SM-7351-RES-0402]  89.28 32.77 0 bottom
R211  0  [SM-7351-RES-0402]  89.28 31.62 0 bottom
R212  0.1ohm1% Sense  [SM_RES_0805_KELV]  105.93 30.55 90 bottom
R213  0  [SM-7351-RES-0402]  61.65 30.35 270 bottom
R214  12.1K, 1%  [SM-7351-RES-0402]  48.51 29.84 180 bottom
R215  2.2K  [SM-7351-RES-0402]  132.08 28.57 90 bottom
R216  1M  [SM-7351-RES-0402]  61.65 28.19 270 bottom
R217  0  [SM-7351-RES-0402]  87.88 27.18 270 bottom
R218  10K, 1%  [SM-7351-RES-0402]  86.74 26.92 90 bottom
R219  4.7K  [SM-7351-RES-0402]  100.72 26.11 270 bottom
R220  22  [SM-7351-RES-0402]  61.65 26.04 90 bottom
R221  2.2K  [SM-7351-RES-0402]  47.81 25.53 270 bottom
R222  30.1K  [SM-7351-RES-0402]  25.99 25.22 0 bottom
R223  0  [SM-7351-RES-0402]  86.74 22.61 0 bottom
R224  51K  [SM-7351-RES-0402]  26.37 22.43 270 bottom
R225  10K  [SM-7351-RES-0402]  63.92 20.87 180 bottom
R226  49.9  [SMD_MELF0102]  74.73 20.83 180 bottom
R227  0  [SM-7351-RES-0402]  45.4 20.57 90 bottom
R228  0  [SM-7351-RES-0402]  44.25 20.57 90 bottom
R229  0  [SM-7351-RES-0402]  41.46 20.57 90 bottom
R230  0  [SM-7351-RES-0402]  40.32 20.57 90 bottom
R231  2.2K  [SM-7351-RES-0402]  132.08 18.54 90 bottom
R232  0  [SM-7351-RES-0402]  96.03 18.11 180 bottom
R233  0  [SM-7351-RES-0402]  93.46 17.98 90 bottom
R234  4.75K, 1%  [SM-7351-RES-0402]  91.52 16.71 90 bottom
R235  4.75K, 1%  [SM-7351-RES-0402]  104.77 15.75 90 bottom
R236  0  [SM-7351-RES-0402]  103.25 15.75 270 bottom
R237  10K, 1%  [SM-7351-RES-0402]  85.87 15.44 180 bottom
R238  0.24ohm1% Sense  [SM_RES_0805_KELV]  59.96 15.01 90 bottom
R239  0  [SM-7351-RES-0402]  18.8 14.61 270 bottom
R240  150  [SM-7351-RES-0402]  125.22 14.22 90 bottom
R241  33  [SM-7351-RES-0402]  85.27 13.97 0 bottom
R242  10K, 1%  [SM-7351-RES-0402]  85.36 7.06 90 bottom
R243  0  [SM-7351-RES-0402]  89.17 3.75 270 bottom
R244  0  [SM-7351-RES-0402]  88.02 3.75 90 bottom
R245  10K, 1%  [SM-7351-RES-0402]  90.31 3.75 90 bottom
RP1  33x8  [SM_RPAK_EXB-2HV]  34.54 37.47 180 top
RP2  33x8  [SM_RPAK_EXB-2HV]  39.24 37.47 180 top
RP3  33x8  [SM_RPAK_EXB-2HV]  43.81 37.47 180 top
RP4  33x8  [SM_RPAK_EXB-2HV]  48.51 37.47 180 top
RP5  33x8  [SM_RPAK_EXB-2HV]  83.88 13.46 270 top
RP6  33x8  [SM_RPAK_EXB-2HV]  83.88 8.71 270 top
RP7  33x8  [SM_RPAK_EXB-2HV]  85.71 10.82 90 bottom
SW1  B3SL  [SW_B3SL-1022P]  129.15 49.22 270 top
SW2  B3SL  [SW_B3SL-1022P]  129.15 39.42 270 top
SW3  B3SL  [SW_B3SL-1022P]  129.15 29.62 270 top
SW4  B3SL  [SW_B3SL-1022P]  129.15 19.81 270 top
SW5  B3SL  [SW_B3SL-1022P]  129.29 58.67 90 bottom
SW6  B3SL  [SW_B3SL-1022P]  128.4 47.12 180 bottom
SW7  B3SL  [SW_B3SL-1022P]  129.41 12.32 270 bottom
TP1  TP1mm  [TP_SMD1MMCIRCLE]  34.94 58.62 180 bottom
TP2  TP  [TH_TP_5002]  34.16 53.62 180 bottom
TP3  TP1mm  [TP_SMD1MMCIRCLE]  73.36 52.17 180 bottom
TP4  TP1mm  [TP_SMD1MMCIRCLE]  73.46 49.78 180 bottom
TP5  TP  [TH_TP_5002]  118.11 48.51 180 bottom
TP6  TP1mm  [TP_SMD1MMCIRCLE]  71.3 47.88 180 bottom
TP7  TP1mm  [TP_SMD1MMCIRCLE]  102.29 39.75 180 bottom
TP8  TP1mm  [TP_SMD1MMCIRCLE]  60.26 34.92 180 bottom
TP9  TP1mm  [TP_SMD1MMCIRCLE]  105.55 33.85 180 bottom
TP10  TP1mm  [TP_SMD1MMCIRCLE]  85.47 26.54 180 bottom
TP11  TP  [TH_TP_5002]  112.01 25.4 180 bottom
TP12  TP1mm  [TP_SMD1MMCIRCLE]  24.97 23.06 180 bottom
TP13  TP  [TH_TP_5002]  98.89 18.87 180 bottom
TP14  TP1mm  [TP_SMD1MMCIRCLE]  34.09 14.22 180 bottom
TP15  TP1mm  [TP_SMD1MMCIRCLE]  27.18 13.34 0 bottom
TP16  TP1mm  [TP_SMD1MMCIRCLE]  34.09 12.83 180 bottom
TP17  TP1mm  [TP_SMD1MMCIRCLE]  27.18 11.56 0 bottom
TP18  TP1mm  [TP_SMD1MMCIRCLE]  89.42 9.72 180 bottom
TP19  TP1mm  [TP_SMD1MMCIRCLE]  27.18 9.65 180 bottom
TP20  TP1mm  [TP_SMD1MMCIRCLE]  90.31 6.93 180 bottom
TP21  TP1mm  [TP_SMD1MMCIRCLE]  38.44 6.17 180 bottom
TP22  TP1mm  [TP_SMD1MMCIRCLE]  89.04 5.53 180 bottom
TP23  TP1mm  [TP_SMD1MMCIRCLE]  85.45 4.32 90 bottom
TP24  TP1mm  [TP_SMD1MMCIRCLE]  39.24 3.17 180 bottom
TP25  TP1mm  [TP_SMD1MMCIRCLE]  85.47 2.9 90 bottom
U1  TPD6E001  [U_10_RSE]  104.77 65.66 0 top
U2  TPD2E001  [U_5_DRL]  100.46 58.8 270 top
U3  TPS78633  [SOT223_6PIN]  111.69 54.79 0 top
U4  SN74LVC1G00DCK  [U_5_DCK]  48.39 52.83 0 top
U5  SN74LVC2G07  [U_6_DCK]  42.65 51.83 90 top
U6  SN74LVC1G07  [U_5_DCK]  86.61 46.23 0 top
U7  TPS61081DRC  [U_10_DRC]  28.15 39.95 270 top
U8  CAT24C256W  [SOIC_8]  104.14 24.26 0 top
U9  93LC56B  [SOT23-6]  47.88 21.08 0 top
U10  LIS331DLH  [LGA16PIN_3X3]  95.88 17.02 270 top
U11  SN74AVC4T245  [U_16_PW]  53.72 15.62 90 top
U12  SN74AVC4T245  [U_16_PW]  57.15 8.64 90 top
U13  TPS79518  [SOT223_6PIN]  30.94 7.95 180 top
U14  TPS51200  [DRCPSO_10PIN]  89.28 3.3 0 top
U15  TPD4S012  [U_6_DRY]  39.58 62.94 180 bottom
U16  USB2412_QFN28  [QFN28_5X5]  43.82 56.79 180 bottom
U17  TPD4S012  [U_6_DRY]  23.45 54.69 270 bottom
U18  TPS2051BD  [U_8_D]  15.96 51.77 180 bottom
U19  SN74AUP2G08  [U_8_DCU]  112.78 50.42 180 bottom
U20  TPS63010  [U_20_DSBGA]  21.8 48.72 0 bottom
U21  TPS71718  [SMDSC70-5]  122.3 46.74 180 bottom
U22  XC6218P182HR-G  [USP1_2SQR-3]  19.26 45.29 0 bottom
U23  AR8031_AL1A  [QFN48]  96.01 39.75 270 bottom
U24  AR8031_AL1A  [QFN48]  55.63 39.75 270 bottom
U25  TPS65910A3  [U_48_RSL]  114.05 39.24 270 bottom
U26  AM335X_ZCZ  [BGA15X15-324-55M]  73.54 33.01 90 bottom
U27  TPS79501  [SOT223_6PIN]  29.17 30.43 180 bottom
U28  FT2232HL  [LQFP64PIN]  40.67 28.83 180 bottom
U29  SN74AVC4T245  [U_16_PW]  53.95 22.68 0 bottom
U30  DLW5BTN501SQ2L  [DLW5BTN501SQ2]  120.4 16.51 0 bottom
U31  TLV320AIC3106  [VQFN48_RGZ]  39.83 12.21 180 bottom
U32  MT41J128M16JT-125  [BGA14X10-96]  73.91 10.79 270 bottom
Y1  25MHz  [SM_OSC_ABM3]  56.26 47.88 0 top
Y2  32.768Khz,5+/-23ppm  [SOJ2_4X3_6-12]  21.42 34.75 90 top
Y3  24MHz  [XTAL4_3P2X2P5_SMD]  49.28 60.58 270 bottom
Y4  25MHz  [SM_OSC_ABM3]  101.55 49.1 0 bottom
Y5  12MHz,+/-50ppm  [XTAL4_3P2X5SMD]  46.1 38.35 180 bottom
Y6  24MHz  [XTAL4_3P2X2P5_SMD]  58.48 28.96 270 bottom
Y7  32.768KHz MC-306  [MC-306]  94.11 27.81 0 bottom

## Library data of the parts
A1 = WIFI_BTModule_LBEE5ZSTNC-523
ANT1 = ANTENNA_WLAN_2.4GHZ
C1 C5 C11 C13 C15 C16 C18 C24 C34 C36 C38 C47 C58 C65 C71 C73 C89 C124 C125 C133 C138 C145 C146 C150 C153 C155 C167 C183 C187 C189 C194 C196 C198 C199 C205 C214 C218 C222-C224 C241 C242 C246 C248 C251 C253 C265 C266 C272 C276 C278 C280 C281 = 0.1uFCapacitor16V10%0402: User Part Number: USERPART#; Tolerance: TOLERANCE
C2 C3 C12 C23 C26 C33 C42 C46 C63 C76 C77 C134 C176 C193 = 4.7uFCapacitor16V10%0603
C4 C6 = 18pFCapacitor10V2%0402: User Part Number: USERPART#; Tolerance: TOLERANCE
C7 C14 C32 C35 C37 C39 C41 C83 C122 C137 C154 C195 C197 C217 C220 C228 C243 C252 C254 C256 C263 C279 = 1uFCapacitor10V10%0402: User Part Number: USERPART#; Tolerance: TOLERANCE
C8-C10 C17 = 0.1uFCapacitor50V10%0402: User Part Number: USERPART#; Tolerance: TOLERANCE
C19 C20 C45 C50-C53 C55-C57 C59-C62 C69 C70 C72 C78-C80 C82 C84 C87 C90-C96 C98-C106 C115 C116 C126 C127 C136 C149 C151 C156 C157 C159-C164 C166 C170 C180 C184 C188 C190-C192 C206 C215 C225 C230 C231 C236 C239 C255 C258 C259 C264 C274 C275 = 0.01uFCapacitor16V10%0402: User Part Number: USERPART#; Tolerance: TOLERANCE
C21 C22 = 22uFCapacitor16V10%0805
C25 C207 = 2.2uFCapacitor10V20%smd0402: User Part Number: USERPART#; Tolerance: TOLERANCE
C27-C30 C43 C44 C49 C67 C74 C97 C117 C123 C132 C139-C141 C158 C177-C179 C182 C186 C200 C203 C204 C216 C219 C235 C244 C261 C267 C270 C273 C277 = 10uFCapacitor16V10%0805
C31 C210-C213 C221 C227 C232 C238 = 2.2uFCapacitor6.3V20%smdX5R0402: User Part Number: USERPART#; Tolerance: TOLERANCE
C40 C48 C54 C66 = 0.1uFCapacitor16V10%0402
C64 = 47nFCapacitor16V10%0402: User Part Number: USERPART#; Tolerance: TOLERANCE
C68 C81 C226 C229 C237 C240 = 470pFCapacitor25V10%0402: User Part Number: USERPART#; Tolerance: TOLERANCE
C75 = 4.7uF50V20%SMD0805
C85 C86 C107 = 0.01uFCapacitor16V10%0402: User Part Number: USERPART#; Tolerance: TOLERANCE; signal model: 33OHMRESISTOR1_16W5_0402_SM_735_33
C88 C171 = 0.001uFCapacitor50V5%0402: User Part Number: USERPART#; Tolerance: TOLERANCE
C108-C114 C118-C121 C128-C131 C142-C144 C147 C148 C165 C168 C169 C172-C175 C260 C268 C269 C271 = 0.1uFCapacitor6.3V10%0201
C135 C152 = 2.2uF16V10%SMD0805
C181 C185 = 47uFCapacitor16V20%1206
C201 C202 C208 C209 C233 C234 = 27pFCapacitor10V5%0402: User Part Number: USERPART#; Tolerance: TOLERANCE
C245 C250 = 18pFCapacitor50V5%0402: User Part Number: USERPART#; Tolerance: TOLERANCE
C247 C249 = 22pFCapacitor50V10%SMD0402: User Part Number: USERPART#; Tolerance: TOLERANCE
C257 = 15pFCapacitor50V10%smd0402: User Part Number: USERPART#; Tolerance: TOLERANCE
C262 = 100uFCapacitor16V20%ElectroPoly
D1-D5 = LED_Green
D6 = Diode_Zener_5.1V_100mW
D7 = Diode_SMCJ7.0CA
D8 = Diode_5ARect
F1 = Fuse_4A
FB1 = FerBead_0
FB2 = FerBead_11
FB3 = FerBead_9
FB4 = FerBead_10
FB5 = FerBead_8
FB6 = FerBead_12
FB7 FB8 FB12 = FerBead_180ohm200mA
FB9 = FerBead_7
FB10 = FerBead_2
FB11 = FerBead_1
FB13 = FerBead_3
FB14 = FerriteBead_3
FB15 = FerriteBead_2
FB16 = FerriteBead_0
FB17 = FerriteBead_1
FB18 = FerBead_4
FB19 = FerBead_6
FB20 = FerBead_5
J1 = conn_40pin_0.5mm_FFC
J2 = Conn_FFC_0522710679
J3 = Conn_MicroUSBAB
J4 = Conn_microSD_8: User Part Number: X; Tolerance: X
J5 = Connector_USB_A
J6 J7 = ConnectorRJ45_Gigabit
J8 = Header_4x1
J9 = Conn_PwrJack_RAPC712
J10 = MM8130-2600RB8
J11 = Header_6x1
J12 = Header10x2_CJTAG
J13 = Conn_3.5mm_SJ3524SMT
L1 L2 = ACM2012
L3 = 4.7uH30%0_1.9Asmd
L4 = 4.7uHInductor30%3_0.1Asmd
L5 = 4.7uH30%0_0.9Asmd
L6-L8 L10 L12 = 2.2uHInductor10%2_1.6Asmd
L9 = 4.7uHInductor30%1_0.7Asmd
L11 = 2.2uHInductor10%2_0.6Asmd
L13 = 5.1nHInductor: User Part Number: USERPART#; Tolerance: TOLERANCE
L14 R17 R20 R21 R29 R54 R55 R72 R73 R75 R77-R80 R84 R85 R87 R91 R92 R109 R115 R117 R122 R124 R128 R137-R140 R143 R167 R173 R187-R189 R201 R210 R211 R213 R217 R223 R227-R230 R232 R233 R236 R239 R243 R244 = ZeroOhmResistor1/16W0402
L15 = 1.3nHInductor
MH1-MH4 = Mounthole_2.286mm
Q1-Q5 = MOSFET_NChan_BSS138
R1-R5 R22 R25 R27 R28 R31-R46 R53 R57 R58 R60-R62 R64 R66 R68 R70 R74 R86 R102 R108 R112 R123 R127 R175 R178 R182-R185 R191 R193 R196 R198 R199 R205 R207 R209 R225 = 10KOhmResistor1/16W0402
R6-R9 = 220ohm1/10W1%smd0402
R10 R216 = 1MOhmResistor1/16W0402
R11 = 470Kohm1/16W1%SMD0402
R12 R14 R26 R47 R49 R98 R100 R101 R103-R106 R120 R125 R149-R164 = 100KOhmResistor1/16W0402
R13 R59 R76 R82 R83 R93 R95 R96 R110 R118 R119 R218 R237 R242 R245 = 10KOhmResistor1/10W1%0402
R15 R131 R141 R142 R169 R170 R177 R179 R219 = 4.7KOhmResistor1/16W0402
R16 R90 R234 R235 = 4.75KohmResistor1/16W1%0402
R18 = 180KOhmResistor1/16W0402
R19 = 1.62MOhmResistor1/16W0402
R23 R121 R144 = ZeroOhmResistor1/16W0603
R24 R52 R132 R147 R148 R171 R176 R181 R186 R220 = 22OhmResistor1/16W1%0402
R30 = 1.5KohmResistor1/16W5%smd0402
R48 R63 = 10OhmResistor1/10W0603
R50 = 44.2KOhmResistor1/10W1%0603
R51 R56 R65 R67 R69 R71 R129 R130 R133-R136 R168 R174 R180 R190 R192 R194 R195 R197 R200 R203 R204 R206 R208 = 22OhmResistor1/16W1%0402: signal model: 33OHMRESISTOR1_16W5_0402_SM_735_33
R81 R165 R172 R215 R221 R231 = 2.2KOhmResistor1/16W0402
R88 R89 R241 = 33ohmResistor1/16W5%0402
R94 = 240OhmResistor1/10W1%0402
R97 = 100ohm1/16W1%SMD0402
R99 R214 = 12.1KohmResistor1/16W1%0402
R107 R166 = 1KOhmResistor1/16W0402
R111 R113 R114 R116 R240 = 150ohm1/16W1%SMD0402
R126 = 1.2KohmResistor1/4W5%0805
R145 R146 = 2.37KOhmResistor1/16W1%0402
R202 = 10KOhmResistor1/16W0402: signal model: 33OHMRESISTOR1_16W5_0402_SM_735_33
R212 = 0.1ohm0.33W1%Sense0805
R222 = 30.1Kohm1/16W1%smd0402
R224 = 51Kohm1/16W1%smd0402
R226 = 49.9ohm1/3W1%SMDMELF0102
R238 = 0.24ohm0.25W1%Sense0805
RP1-RP7 = 33ohmx8_1/16W5%smd
SW1-SW7 = Switch_Pushbuttonsmd
TP1 TP3 TP4 TP6-TP10 TP12 TP14-TP25 = Testpoint_SMD1mmCircle
TP2 TP5 TP11 TP13 = TestPointThroughHole
U1 = TPD6E001RSE
U2 = TPD2E001DRL
U3 = TPS78633DCQ
U4 = SN74LVC1G00DCK
U5 = SN74LVC2G07
U6 = SN74LVC1G07
U7 = TPS61081DRC
U8 = CAT24C256W
U9 = 93C46B_SSOT23-6
U10 = LIS331DLH
U11 U12 U29 = SN74AVC4T245
U13 = TPS79518DCQ
U14 = TPS51200
U15 U17 = TPD4S012
U16 = USB2412_QFN28_MKTG_2
U18 = TPS2051BD
U19 = SN74AUP2G08
U20 = TPS63010YFF
U21 = TPS71718
U22 = XC6218P182HR-G
U23 U24 = AR8031-AL1A_QFN48
U25 = TPS65910A3
U26 = AM335X_15mmx15mm
U27 = TPS79501
U28 = FT2232_2
U30 = DLW5BTN501SQ2L
U31 = TLV320AIC3106
U32 = MT41J128M16JT-125
Y1 Y4 = Crystal25MHzABM3
Y2 = SG-3030LC
Y3 = Crystal24MHz18PFsmd
Y5 = Crystal12MHZ_ECS-120-20-30B: Tolerance: TOL*; User Part Number: P/N*
Y6 = Crystal24MHz18PFsmd_0
Y7 = Crystal_SMD32_2

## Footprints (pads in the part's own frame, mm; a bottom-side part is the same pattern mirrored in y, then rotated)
6605814-6
  round 1.422 hole 0.889: 1(0,0) 2(1.27,-2.54) 3(2.54,0) 4(3.81,-2.54) 5(5.08,0) 6(6.35,-2.54) 7(7.62,0) 8(8.89,-2.54) 9(10.16,0) 10(11.43,-2.54)
  round 1.397 hole 1.016: D1(-1.067,-11.43) D2(-1.067,-13.462) D3(12.497,-11.43) D4(12.497,-13.462)
  round 3.81 hole 3.175: M1(0,-8.89) M2(11.43,-8.89)
  round 2.159 hole 1.575: SHLD1(-2.032,-5.842) SHLD2(13.462,-5.842)
ACM2012H
  rect 0.75x0.35 smd: 1(-0.975,0.425) 2(-0.975,-0.425) 3(0.975,-0.425) 4(0.975,0.425)
B520C-13-F
  rect 2.5x3.3 smd: 1(-3.4,0) 2(3.4,0)
BGA14X10-96
  round 0.35 smd: A1(-3.2,6) A2(-2.4,6) A3(-1.6,6) A7(1.6,6) A8(2.4,6) A9(3.2,6) B1(-3.2,5.2) B2(-2.4,5.2) B3(-1.6,5.2) B7(1.6,5.2) B8(2.4,5.2) B9(3.2,5.2) C1(-3.2,4.4) C2(-2.4,4.4) C3(-1.6,4.4) C7(1.6,4.4) C8(2.4,4.4) C9(3.2,4.4) D1(-3.2,3.6) D2(-2.4,3.6) D3(-1.6,3.6) D7(1.6,3.6) D8(2.4,3.6) D9(3.2,3.6) E1(-3.2,2.8) E2(-2.4,2.8) E3(-1.6,2.8) E7(1.6,2.8) E8(2.4,2.8) E9(3.2,2.8) F1(-3.2,2) F2(-2.4,2) F3(-1.6,2) F7(1.6,2) F8(2.4,2) F9(3.2,2) G1(-3.2,1.2) G2(-2.4,1.2) G3(-1.6,1.2) G7(1.6,1.2) G8(2.4,1.2) G9(3.2,1.2) H1(-3.2,0.4) H2(-2.4,0.4) H3(-1.6,0.4) H7(1.6,0.4) H8(2.4,0.4) H9(3.2,0.4) J1(-3.2,-0.4) J2(-2.4,-0.4) J3(-1.6,-0.4) J7(1.6,-0.4) J8(2.4,-0.4) J9(3.2,-0.4) K1(-3.2,-1.2) K2(-2.4,-1.2) K3(-1.6,-1.2) K7(1.6,-1.2) K8(2.4,-1.2) K9(3.2,-1.2) L1(-3.2,-2) L2(-2.4,-2) L3(-1.6,-2) L7(1.6,-2) L8(2.4,-2) L9(3.2,-2) M1(-3.2,-2.8) M2(-2.4,-2.8) M3(-1.6,-2.8) M7(1.6,-2.8) M8(2.4,-2.8) M9(3.2,-2.8) N1(-3.2,-3.6) N2(-2.4,-3.6) N3(-1.6,-3.6) N7(1.6,-3.6) N8(2.4,-3.6) N9(3.2,-3.6) P1(-3.2,-4.4) P2(-2.4,-4.4) P3(-1.6,-4.4) P7(1.6,-4.4) P8(2.4,-4.4) P9(3.2,-4.4) R1(-3.2,-5.2) R2(-2.4,-5.2) R3(-1.6,-5.2) R7(1.6,-5.2) R8(2.4,-5.2) R9(3.2,-5.2) T1(-3.2,-6) T2(-2.4,-6) T3(-1.6,-6) T7(1.6,-6) T8(2.4,-6) T9(3.2,-6)
BGA15X15-324-55M
  round 0.356 smd: A1(-6.8,6.8) A2(-6,6.8) A3(-5.2,6.8) A4(-4.4,6.8) A5(-3.6,6.8) A6(-2.8,6.8) A7(-2,6.8) A8(-1.2,6.8) A9(-0.4,6.8) A10(0.4,6.8) A11(1.2,6.8) A12(2,6.8) A13(2.8,6.8) A14(3.6,6.8) A15(4.4,6.8) A16(5.2,6.8) A17(6,6.8) A18(6.8,6.8) B1(-6.8,6) B2(-6,6) B3(-5.2,6) B4(-4.4,6) B5(-3.6,6) B6(-2.8,6) B7(-2,6) B8(-1.2,6) B9(-0.4,6) B10(0.4,6) B11(1.2,6) B12(2,6) B13(2.8,6) B14(3.6,6) B15(4.4,6) B16(5.2,6) B17(6,6) B18(6.8,6) C1(-6.8,5.2) C2(-6,5.2) C3(-5.2,5.2) C4(-4.4,5.2) C5(-3.6,5.2) C6(-2.8,5.2) C7(-2,5.2) C8(-1.2,5.2) C9(-0.4,5.2) C10(0.4,5.2) C11(1.2,5.2) C12(2,5.2) C13(2.8,5.2) C14(3.6,5.2) C15(4.4,5.2) C16(5.2,5.2) C17(6,5.2) C18(6.8,5.2) D1(-6.8,4.4) D2(-6,4.4) D3(-5.2,4.4) D4(-4.4,4.4) D5(-3.6,4.4) D6(-2.8,4.4) D7(-2,4.4) D8(-1.2,4.4) D9(-0.4,4.4) D10(0.4,4.4) D11(1.2,4.4) D12(2,4.4) D13(2.8,4.4) D14(3.6,4.4) D15(4.4,4.4) D16(5.2,4.4) D17(6,4.4) D18(6.8,4.4) E1(-6.8,3.6) E2(-6,3.6) E3(-5.2,3.6) E4(-4.4,3.6) E5(-3.6,3.6) E6(-2.8,3.6) E7(-2,3.6) E8(-1.2,3.6) E9(-0.4,3.6) E10(0.4,3.6) E11(1.2,3.6) E12(2,3.6) E13(2.8,3.6) E14(3.6,3.6) E15(4.4,3.6) E16(5.2,3.6) E17(6,3.6) E18(6.8,3.6) F1(-6.8,2.8) F2(-6,2.8) F3(-5.2,2.8) F4(-4.4,2.8) F5(-3.6,2.8) F6(-2.8,2.8) F7(-2,2.8) F8(-1.2,2.8) F9(-0.4,2.8) F10(0.4,2.8) F11(1.2,2.8) F12(2,2.8) F13(2.8,2.8) F14(3.6,2.8) F15(4.4,2.8) F16(5.2,2.8) F17(6,2.8) F18(6.8,2.8) G1(-6.8,2) G2(-6,2) G3(-5.2,2) G4(-4.4,2) G5(-3.6,2) G6(-2.8,2) G7(-2,2) G8(-1.2,2) G9(-0.4,2) G10(0.4,2) G11(1.2,2) G12(2,2) G13(2.8,2) G14(3.6,2) G15(4.4,2) G16(5.2,2) G17(6,2) G18(6.8,2) H1(-6.8,1.2) H2(-6,1.2) H3(-5.2,1.2) H4(-4.4,1.2) H5(-3.6,1.2) H6(-2.8,1.2) H7(-2,1.2) H8(-1.2,1.2) H9(-0.4,1.2) H10(0.4,1.2) H11(1.2,1.2) H12(2,1.2) H13(2.8,1.2) H14(3.6,1.2) H15(4.4,1.2) H16(5.2,1.2) H17(6,1.2) H18(6.8,1.2) J1(-6.8,0.4) J2(-6,0.4) J3(-5.2,0.4) J4(-4.4,0.4) J5(-3.6,0.4) J6(-2.8,0.4) J7(-2,0.4) J8(-1.2,0.4) J9(-0.4,0.4) J10(0.4,0.4) J11(1.2,0.4) J12(2,0.4) J13(2.8,0.4) J14(3.6,0.4) J15(4.4,0.4) J16(5.2,0.4) J17(6,0.4) J18(6.8,0.4) K1(-6.8,-0.4) K2(-6,-0.4) K3(-5.2,-0.4) K4(-4.4,-0.4) K5(-3.6,-0.4) K6(-2.8,-0.4) K7(-2,-0.4) K8(-1.2,-0.4) K9(-0.4,-0.4) K10(0.4,-0.4) K11(1.2,-0.4) K12(2,-0.4) K13(2.8,-0.4) K14(3.6,-0.4) K15(4.4,-0.4) K16(5.2,-0.4) K17(6,-0.4) K18(6.8,-0.4) L1(-6.8,-1.2) L2(-6,-1.2) L3(-5.2,-1.2) L4(-4.4,-1.2) L5(-3.6,-1.2) L6(-2.8,-1.2) L7(-2,-1.2) L8(-1.2,-1.2) L9(-0.4,-1.2) L10(0.4,-1.2) L11(1.2,-1.2) L12(2,-1.2) L13(2.8,-1.2) L14(3.6,-1.2) L15(4.4,-1.2) L16(5.2,-1.2) L17(6,-1.2) L18(6.8,-1.2) M1(-6.8,-2) M2(-6,-2) M3(-5.2,-2) M4(-4.4,-2) M5(-3.6,-2) M6(-2.8,-2) M7(-2,-2) M8(-1.2,-2) M9(-0.4,-2) M10(0.4,-2) M11(1.2,-2) M12(2,-2) M13(2.8,-2) M14(3.6,-2) M15(4.4,-2) M16(5.2,-2) M17(6,-2) M18(6.8,-2) N1(-6.8,-2.8) N2(-6,-2.8) N3(-5.2,-2.8) N4(-4.4,-2.8) N5(-3.6,-2.8) N6(-2.8,-2.8) N7(-2,-2.8) N8(-1.2,-2.8) N9(-0.4,-2.8) N10(0.4,-2.8) N11(1.2,-2.8) N12(2,-2.8) N13(2.8,-2.8) N14(3.6,-2.8) N15(4.4,-2.8) N16(5.2,-2.8) N17(6,-2.8) N18(6.8,-2.8) P1(-6.8,-3.6) P2(-6,-3.6) P3(-5.2,-3.6) P4(-4.4,-3.6) P5(-3.6,-3.6) P6(-2.8,-3.6) P7(-2,-3.6) P8(-1.2,-3.6) P9(-0.4,-3.6) P10(0.4,-3.6) P11(1.2,-3.6) P12(2,-3.6) P13(2.8,-3.6) P14(3.6,-3.6) P15(4.4,-3.6) P16(5.2,-3.6) P17(6,-3.6) P18(6.8,-3.6) R1(-6.8,-4.4) R2(-6,-4.4) R3(-5.2,-4.4) R4(-4.4,-4.4) R5(-3.6,-4.4) R6(-2.8,-4.4) R7(-2,-4.4) R8(-1.2,-4.4) R9(-0.4,-4.4) R10(0.4,-4.4) R11(1.2,-4.4) R12(2,-4.4) R13(2.8,-4.4) R14(3.6,-4.4) R15(4.4,-4.4) R16(5.2,-4.4) R17(6,-4.4) R18(6.8,-4.4) T1(-6.8,-5.2) T2(-6,-5.2) T3(-5.2,-5.2) T4(-4.4,-5.2) T5(-3.6,-5.2) T6(-2.8,-5.2) T7(-2,-5.2) T8(-1.2,-5.2) T9(-0.4,-5.2) T10(0.4,-5.2) T11(1.2,-5.2) T12(2,-5.2) T13(2.8,-5.2) T14(3.6,-5.2) T15(4.4,-5.2) T16(5.2,-5.2) T17(6,-5.2) T18(6.8,-5.2) U1(-6.8,-6) U2(-6,-6) U3(-5.2,-6) U4(-4.4,-6) U5(-3.6,-6) U6(-2.8,-6) U7(-2,-6) U8(-1.2,-6) U9(-0.4,-6) U10(0.4,-6) U11(1.2,-6) U12(2,-6) U13(2.8,-6) U14(3.6,-6) U15(4.4,-6) U16(5.2,-6) U17(6,-6) U18(6.8,-6) V1(-6.8,-6.8) V2(-6,-6.8) V3(-5.2,-6.8) V4(-4.4,-6.8) V5(-3.6,-6.8) V6(-2.8,-6.8) V7(-2,-6.8) V8(-1.2,-6.8) V9(-0.4,-6.8) V10(0.4,-6.8) V11(1.2,-6.8) V12(2,-6.8) V13(2.8,-6.8) V14(3.6,-6.8) V15(4.4,-6.8) V16(5.2,-6.8) V17(6,-6.8) V18(6.8,-6.8)
